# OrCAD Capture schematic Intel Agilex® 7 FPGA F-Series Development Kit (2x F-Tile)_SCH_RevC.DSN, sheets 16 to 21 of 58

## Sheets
16 PG16 AGX BANK 3A - General IOs: size C
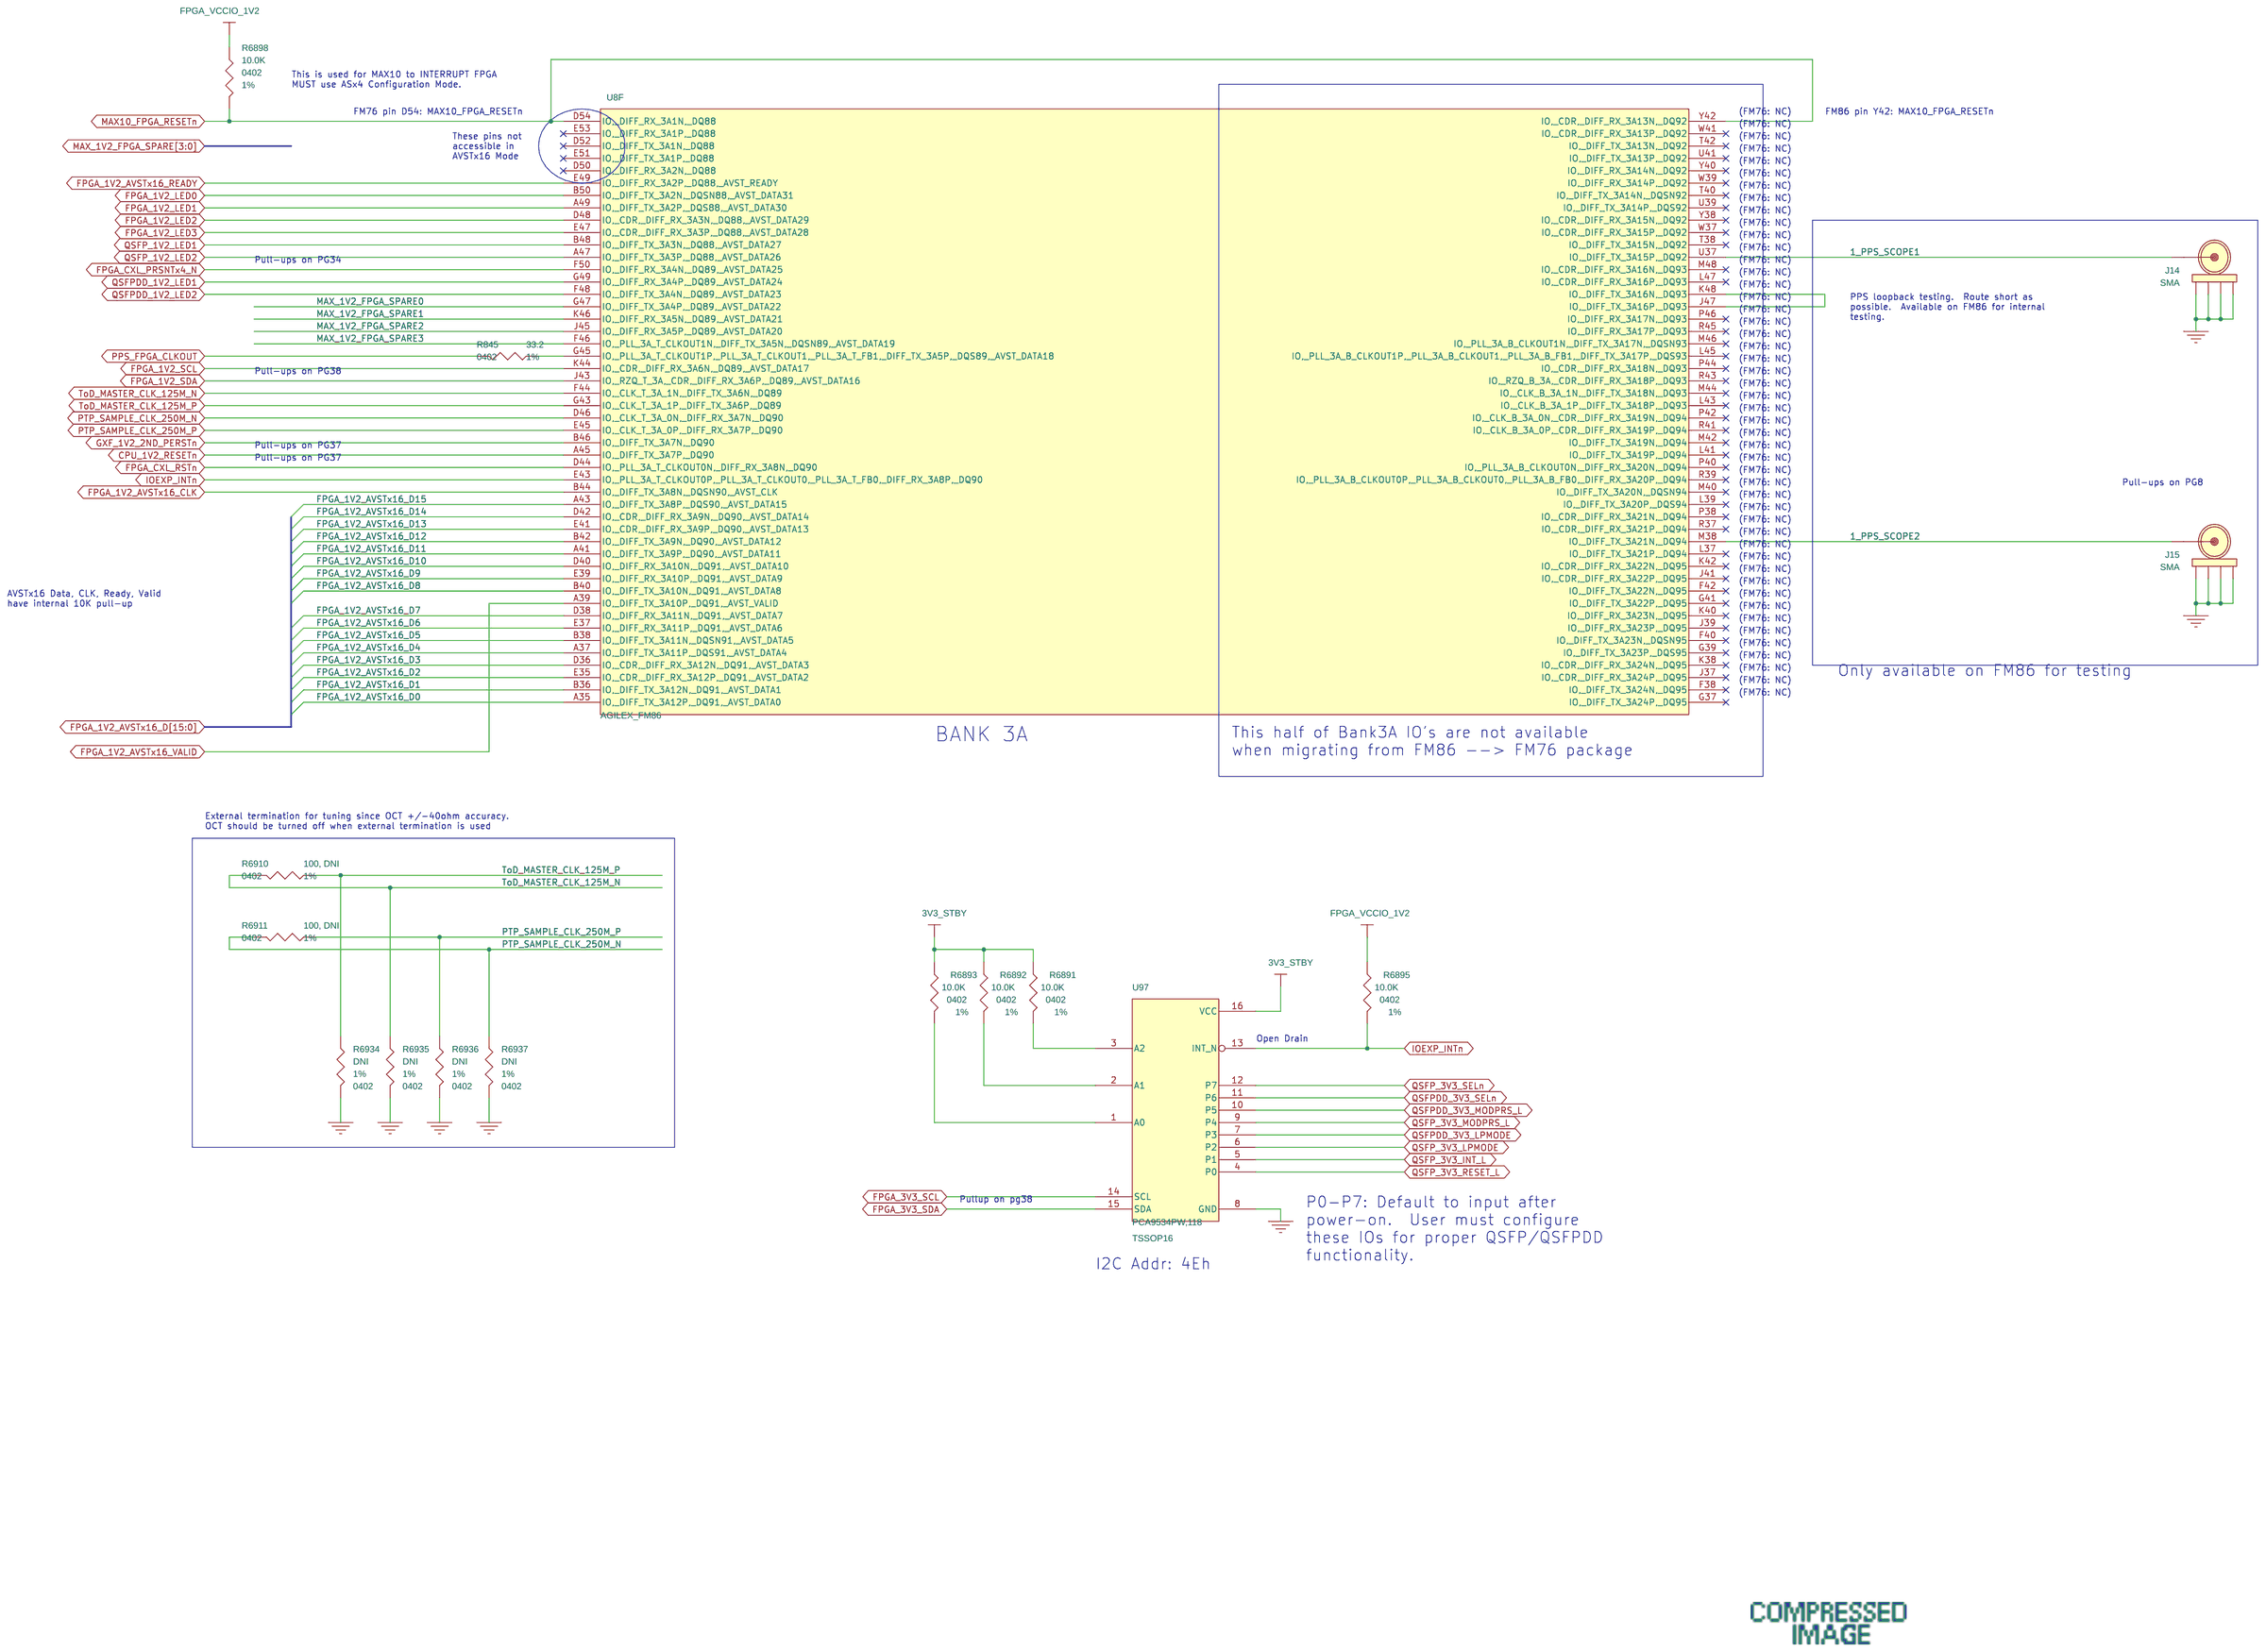
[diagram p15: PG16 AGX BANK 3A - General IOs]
17 PG17 AGX BANK 3B - Unused IOs: size C
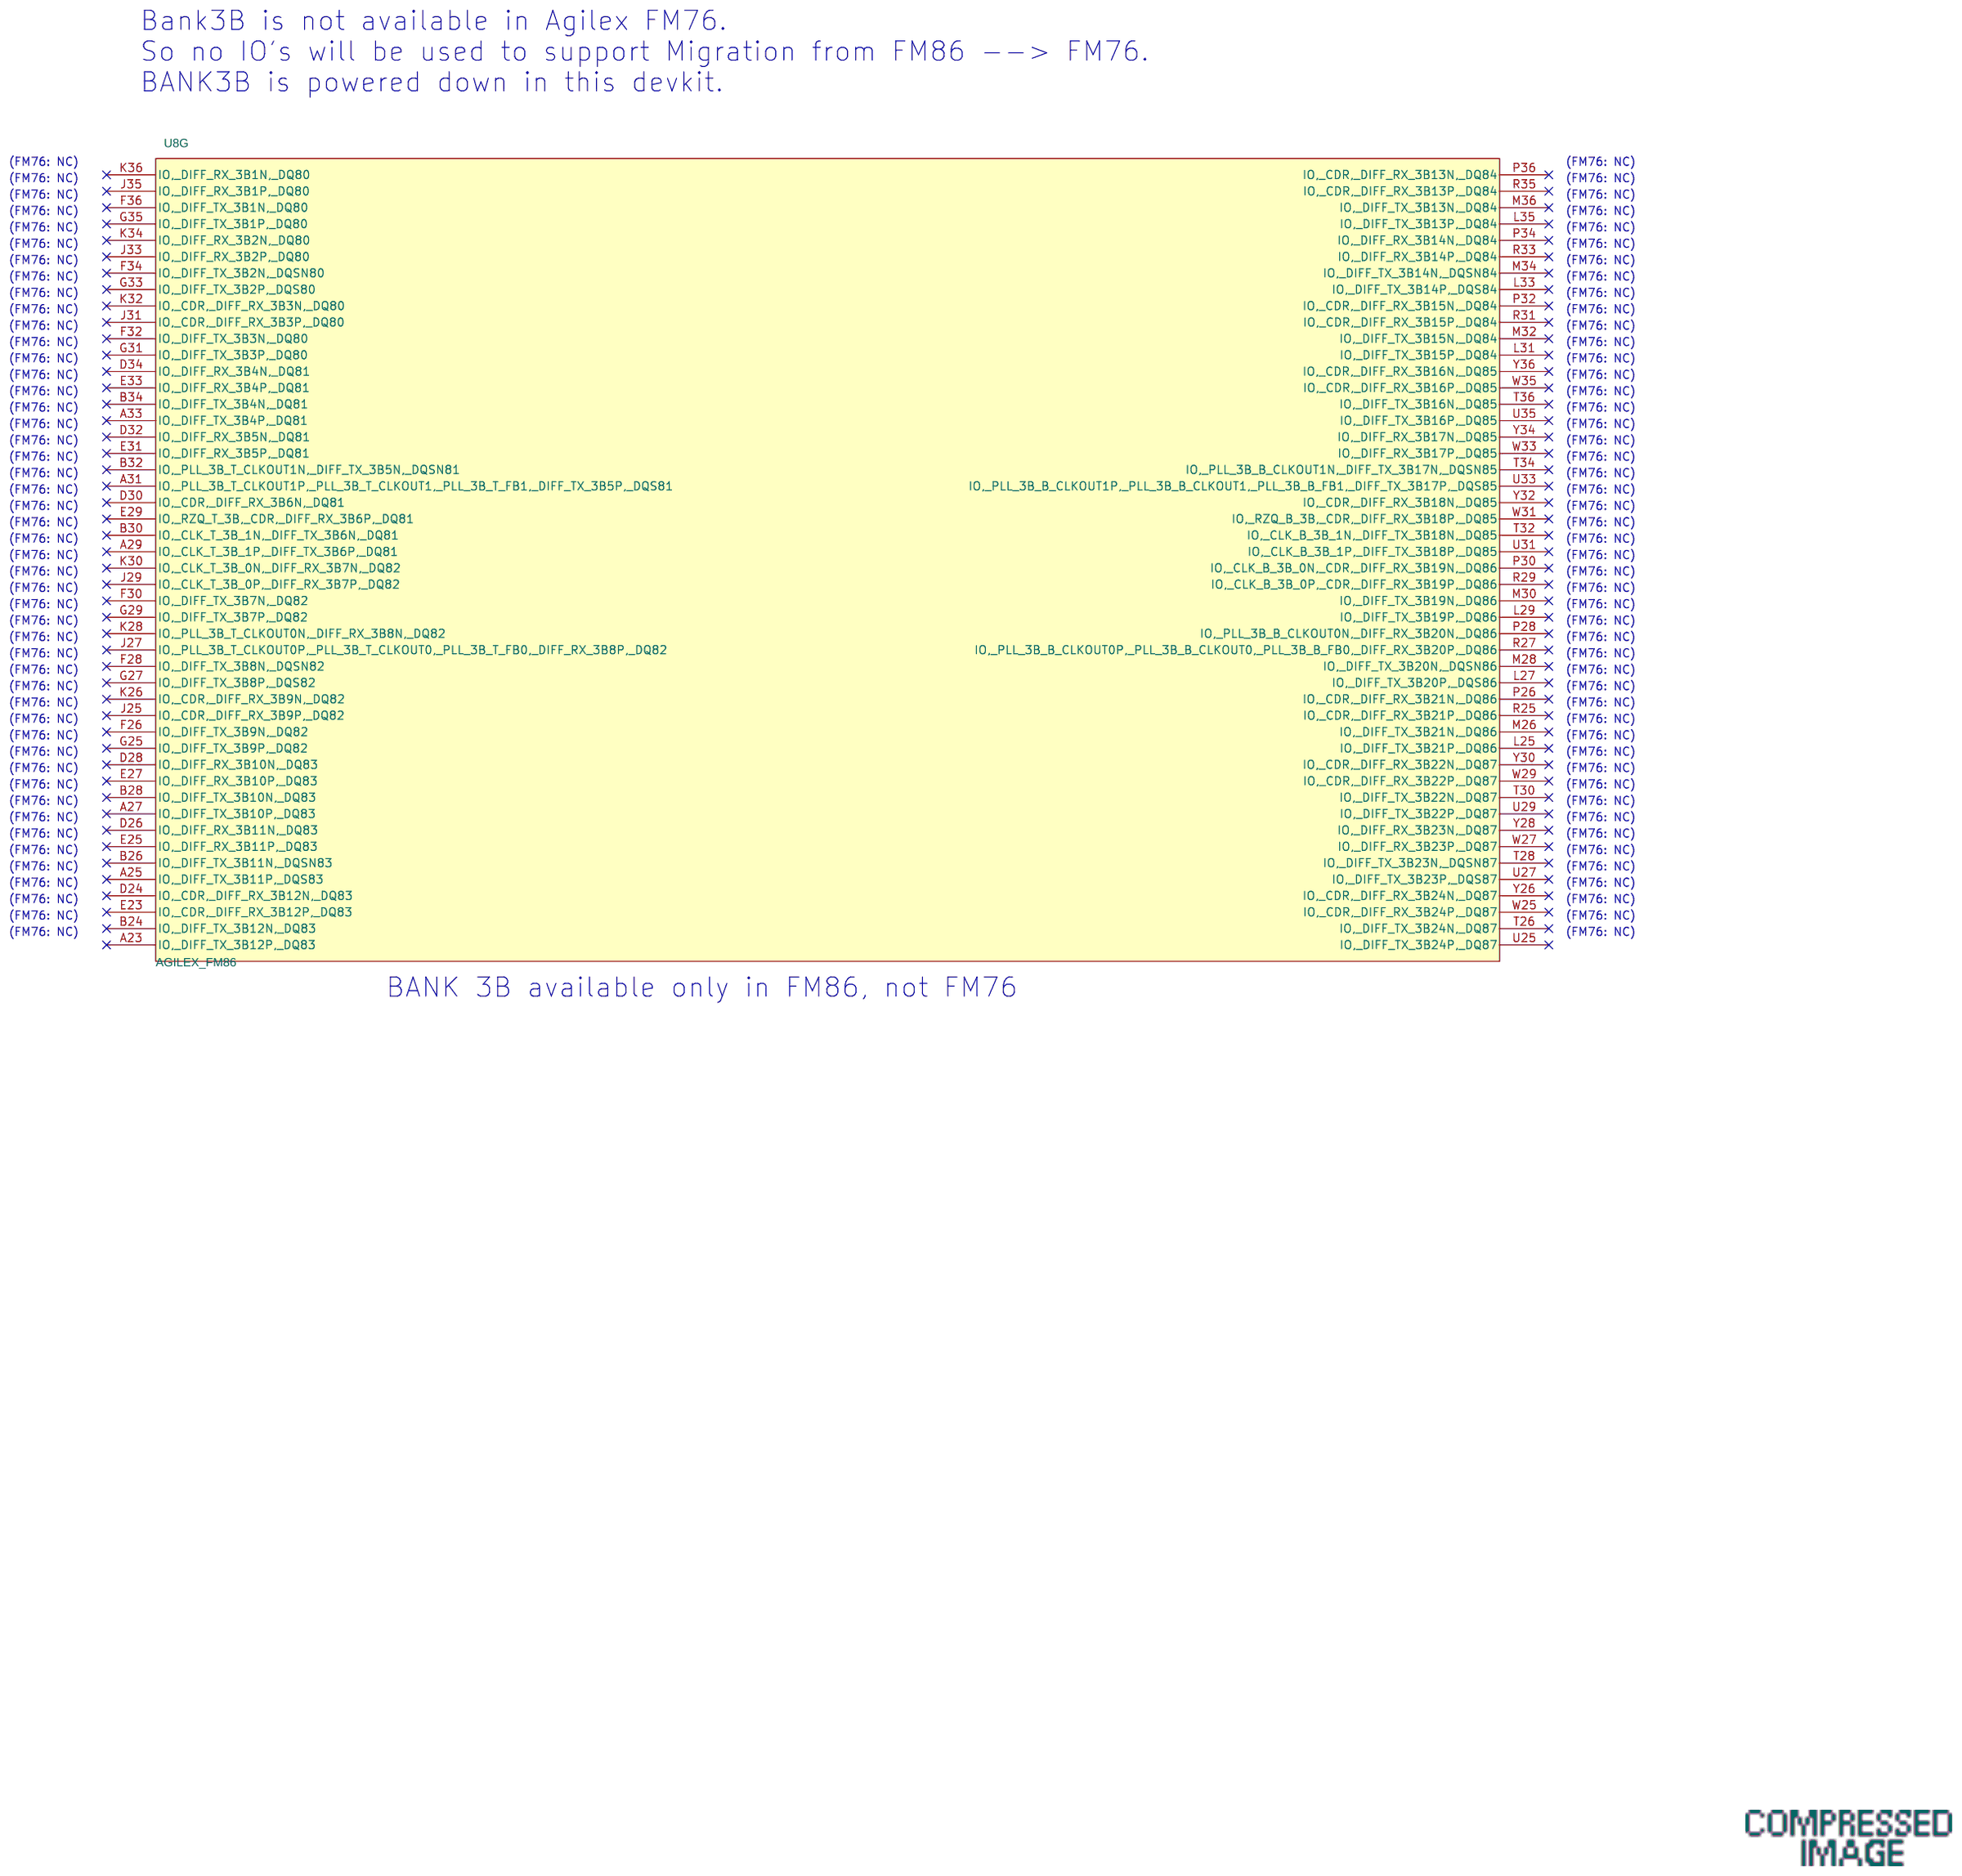
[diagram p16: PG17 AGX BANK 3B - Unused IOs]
18 PG18 AGX BANK 3C - Unused IOs: size C
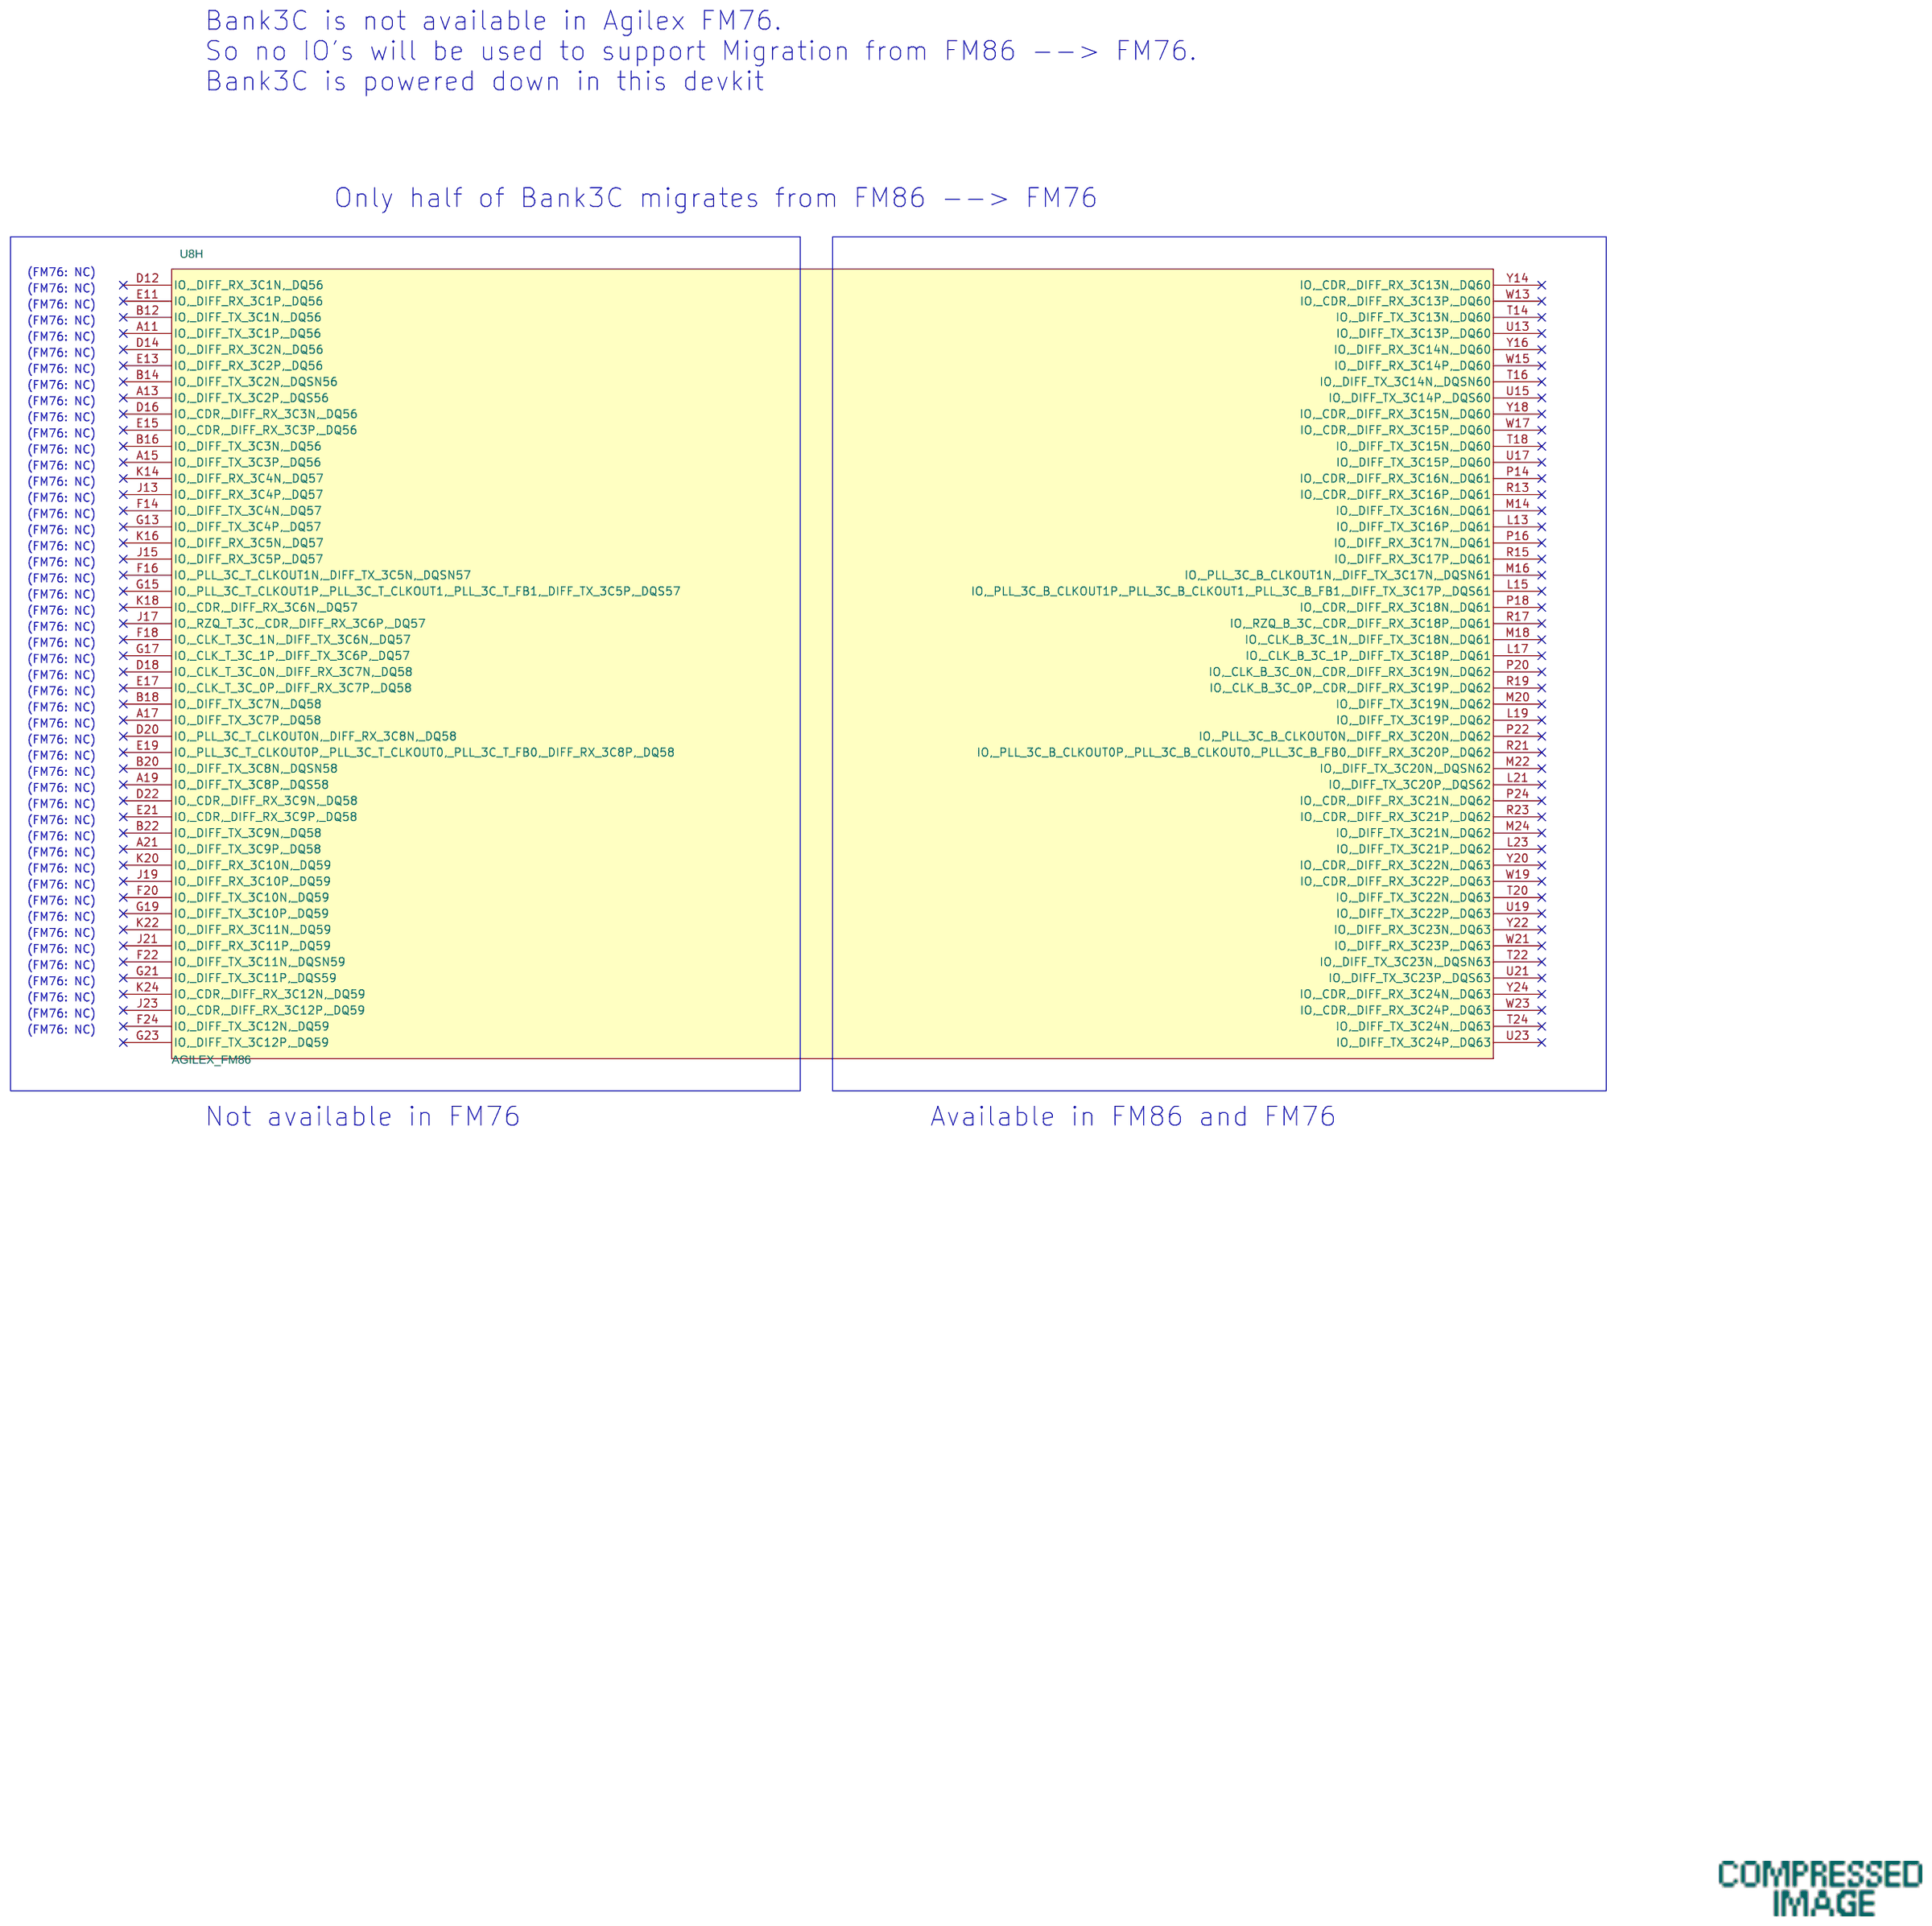
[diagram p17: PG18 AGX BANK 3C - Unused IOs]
19 PG19 AGX BANK 3D - DDR4 COMP: size C
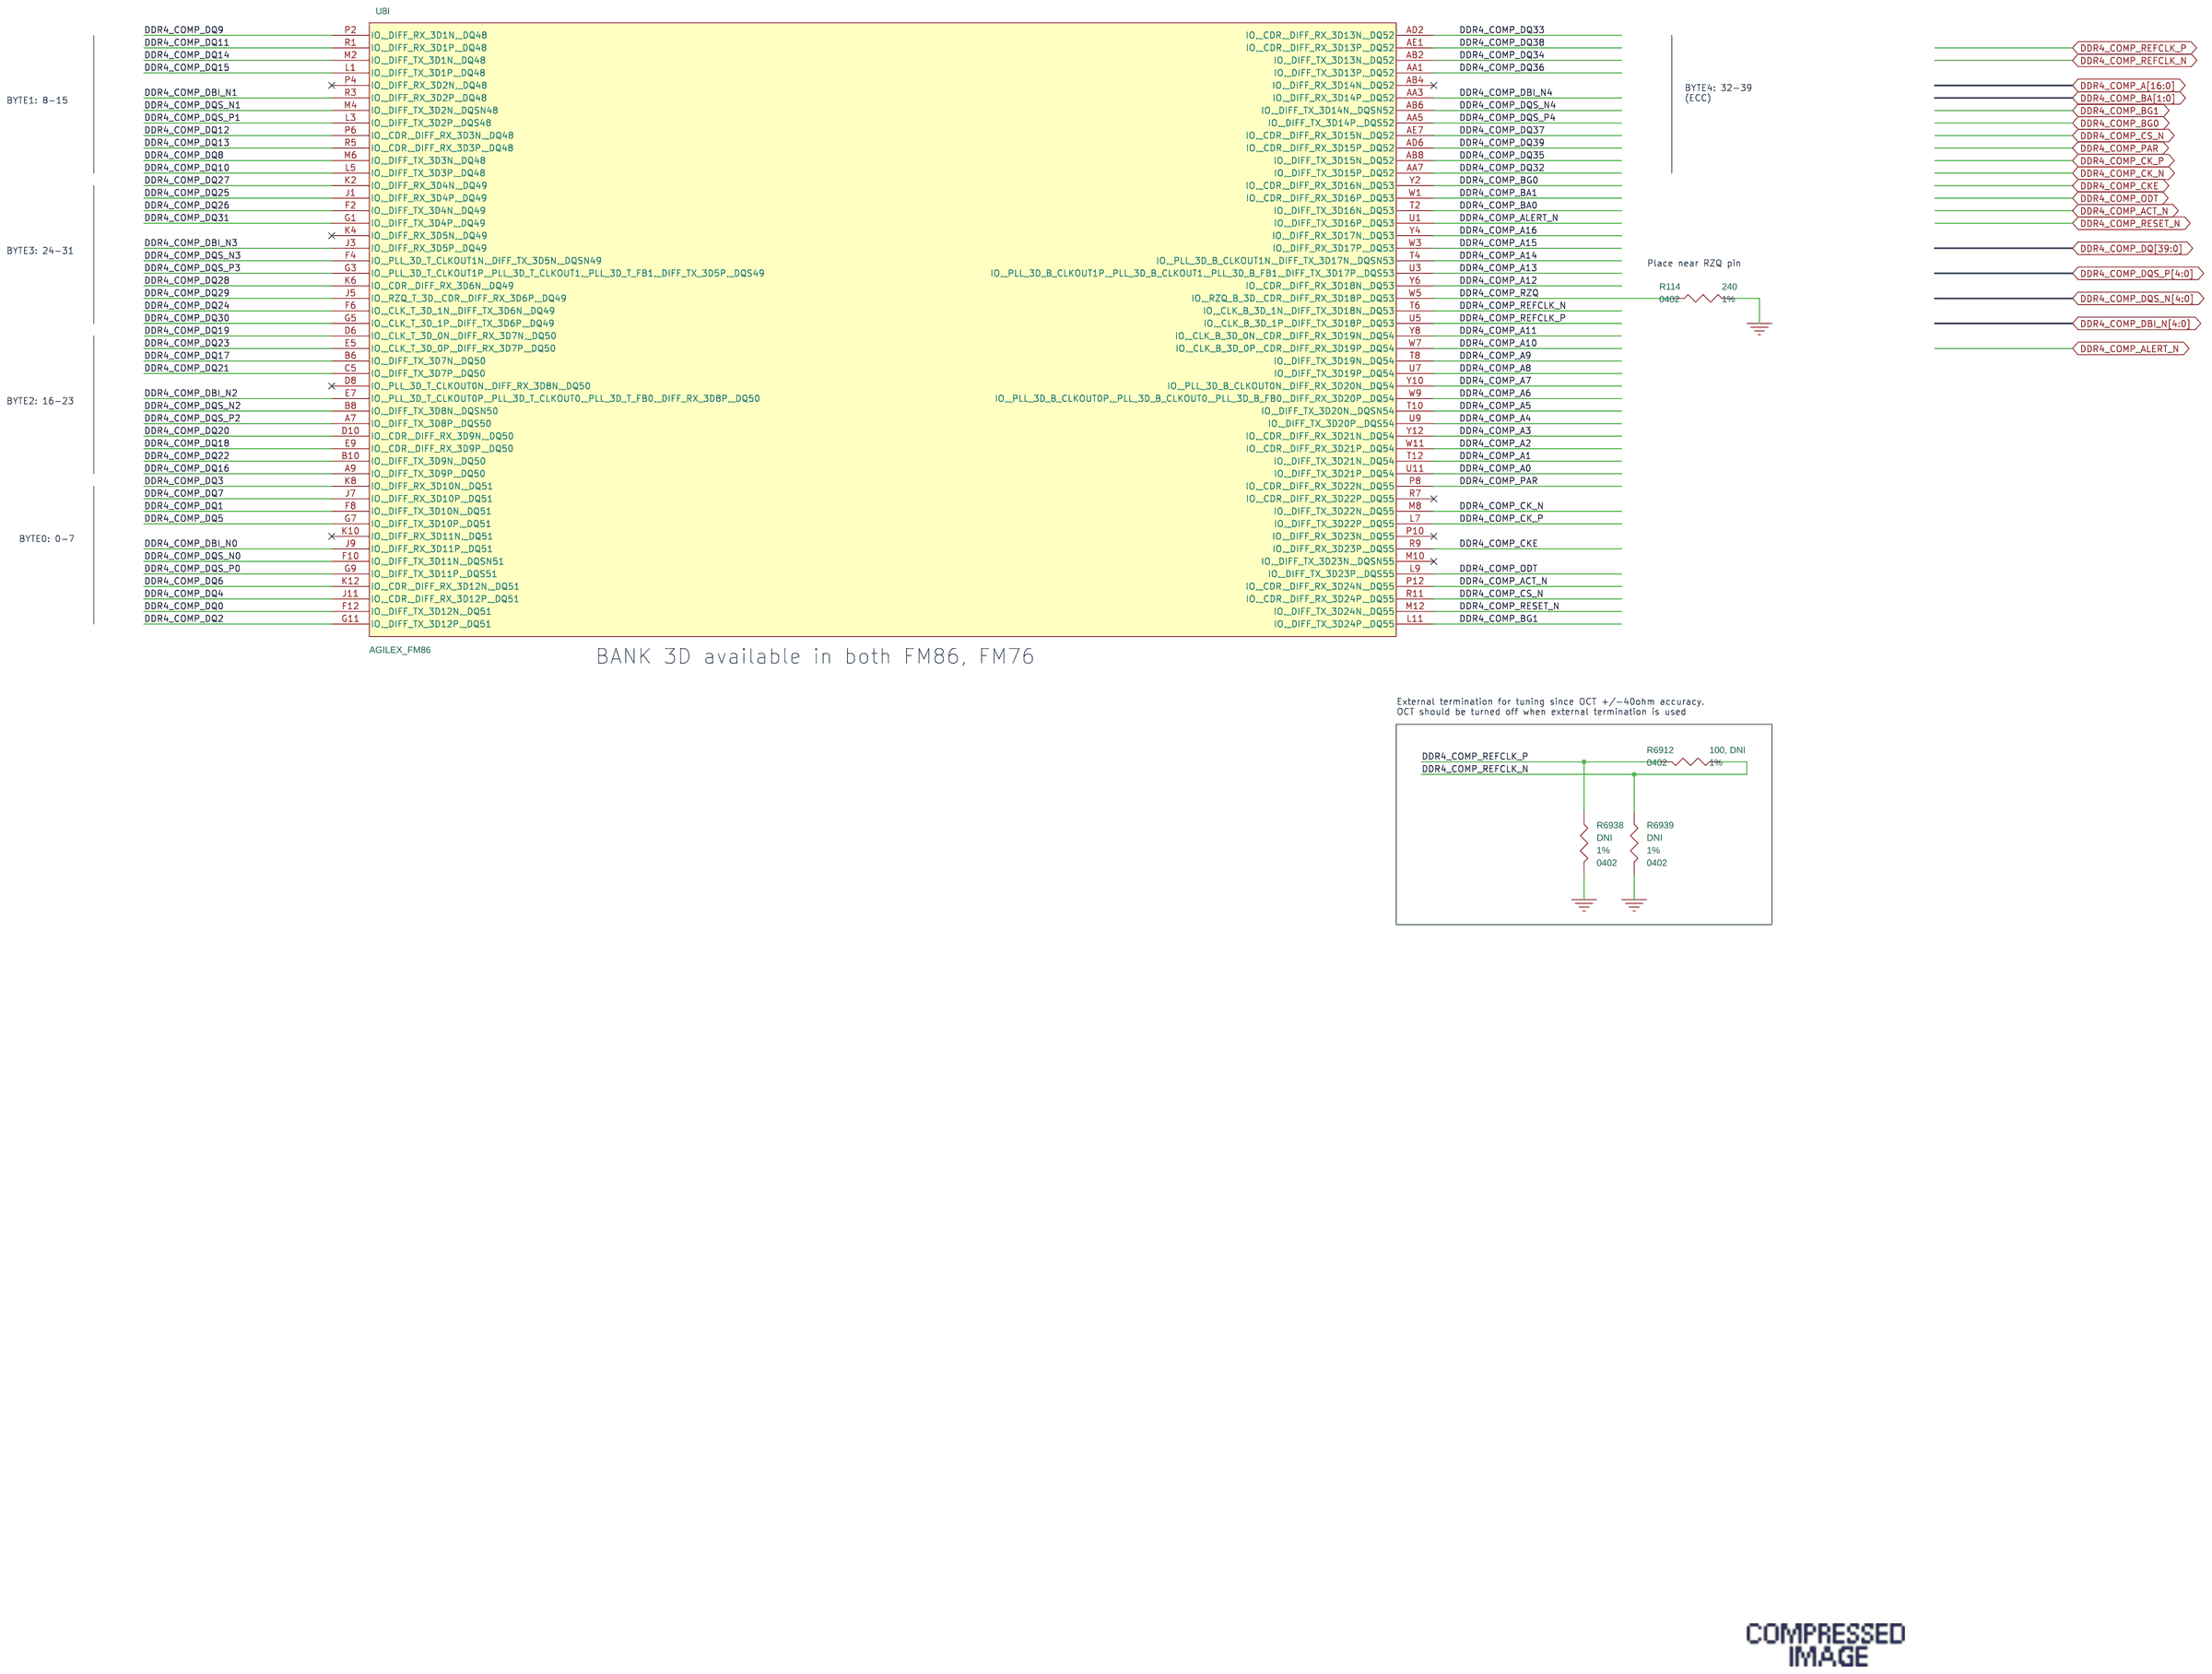
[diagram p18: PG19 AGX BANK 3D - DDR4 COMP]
20 PG20 AGX F-TILE BANK 12C: size C
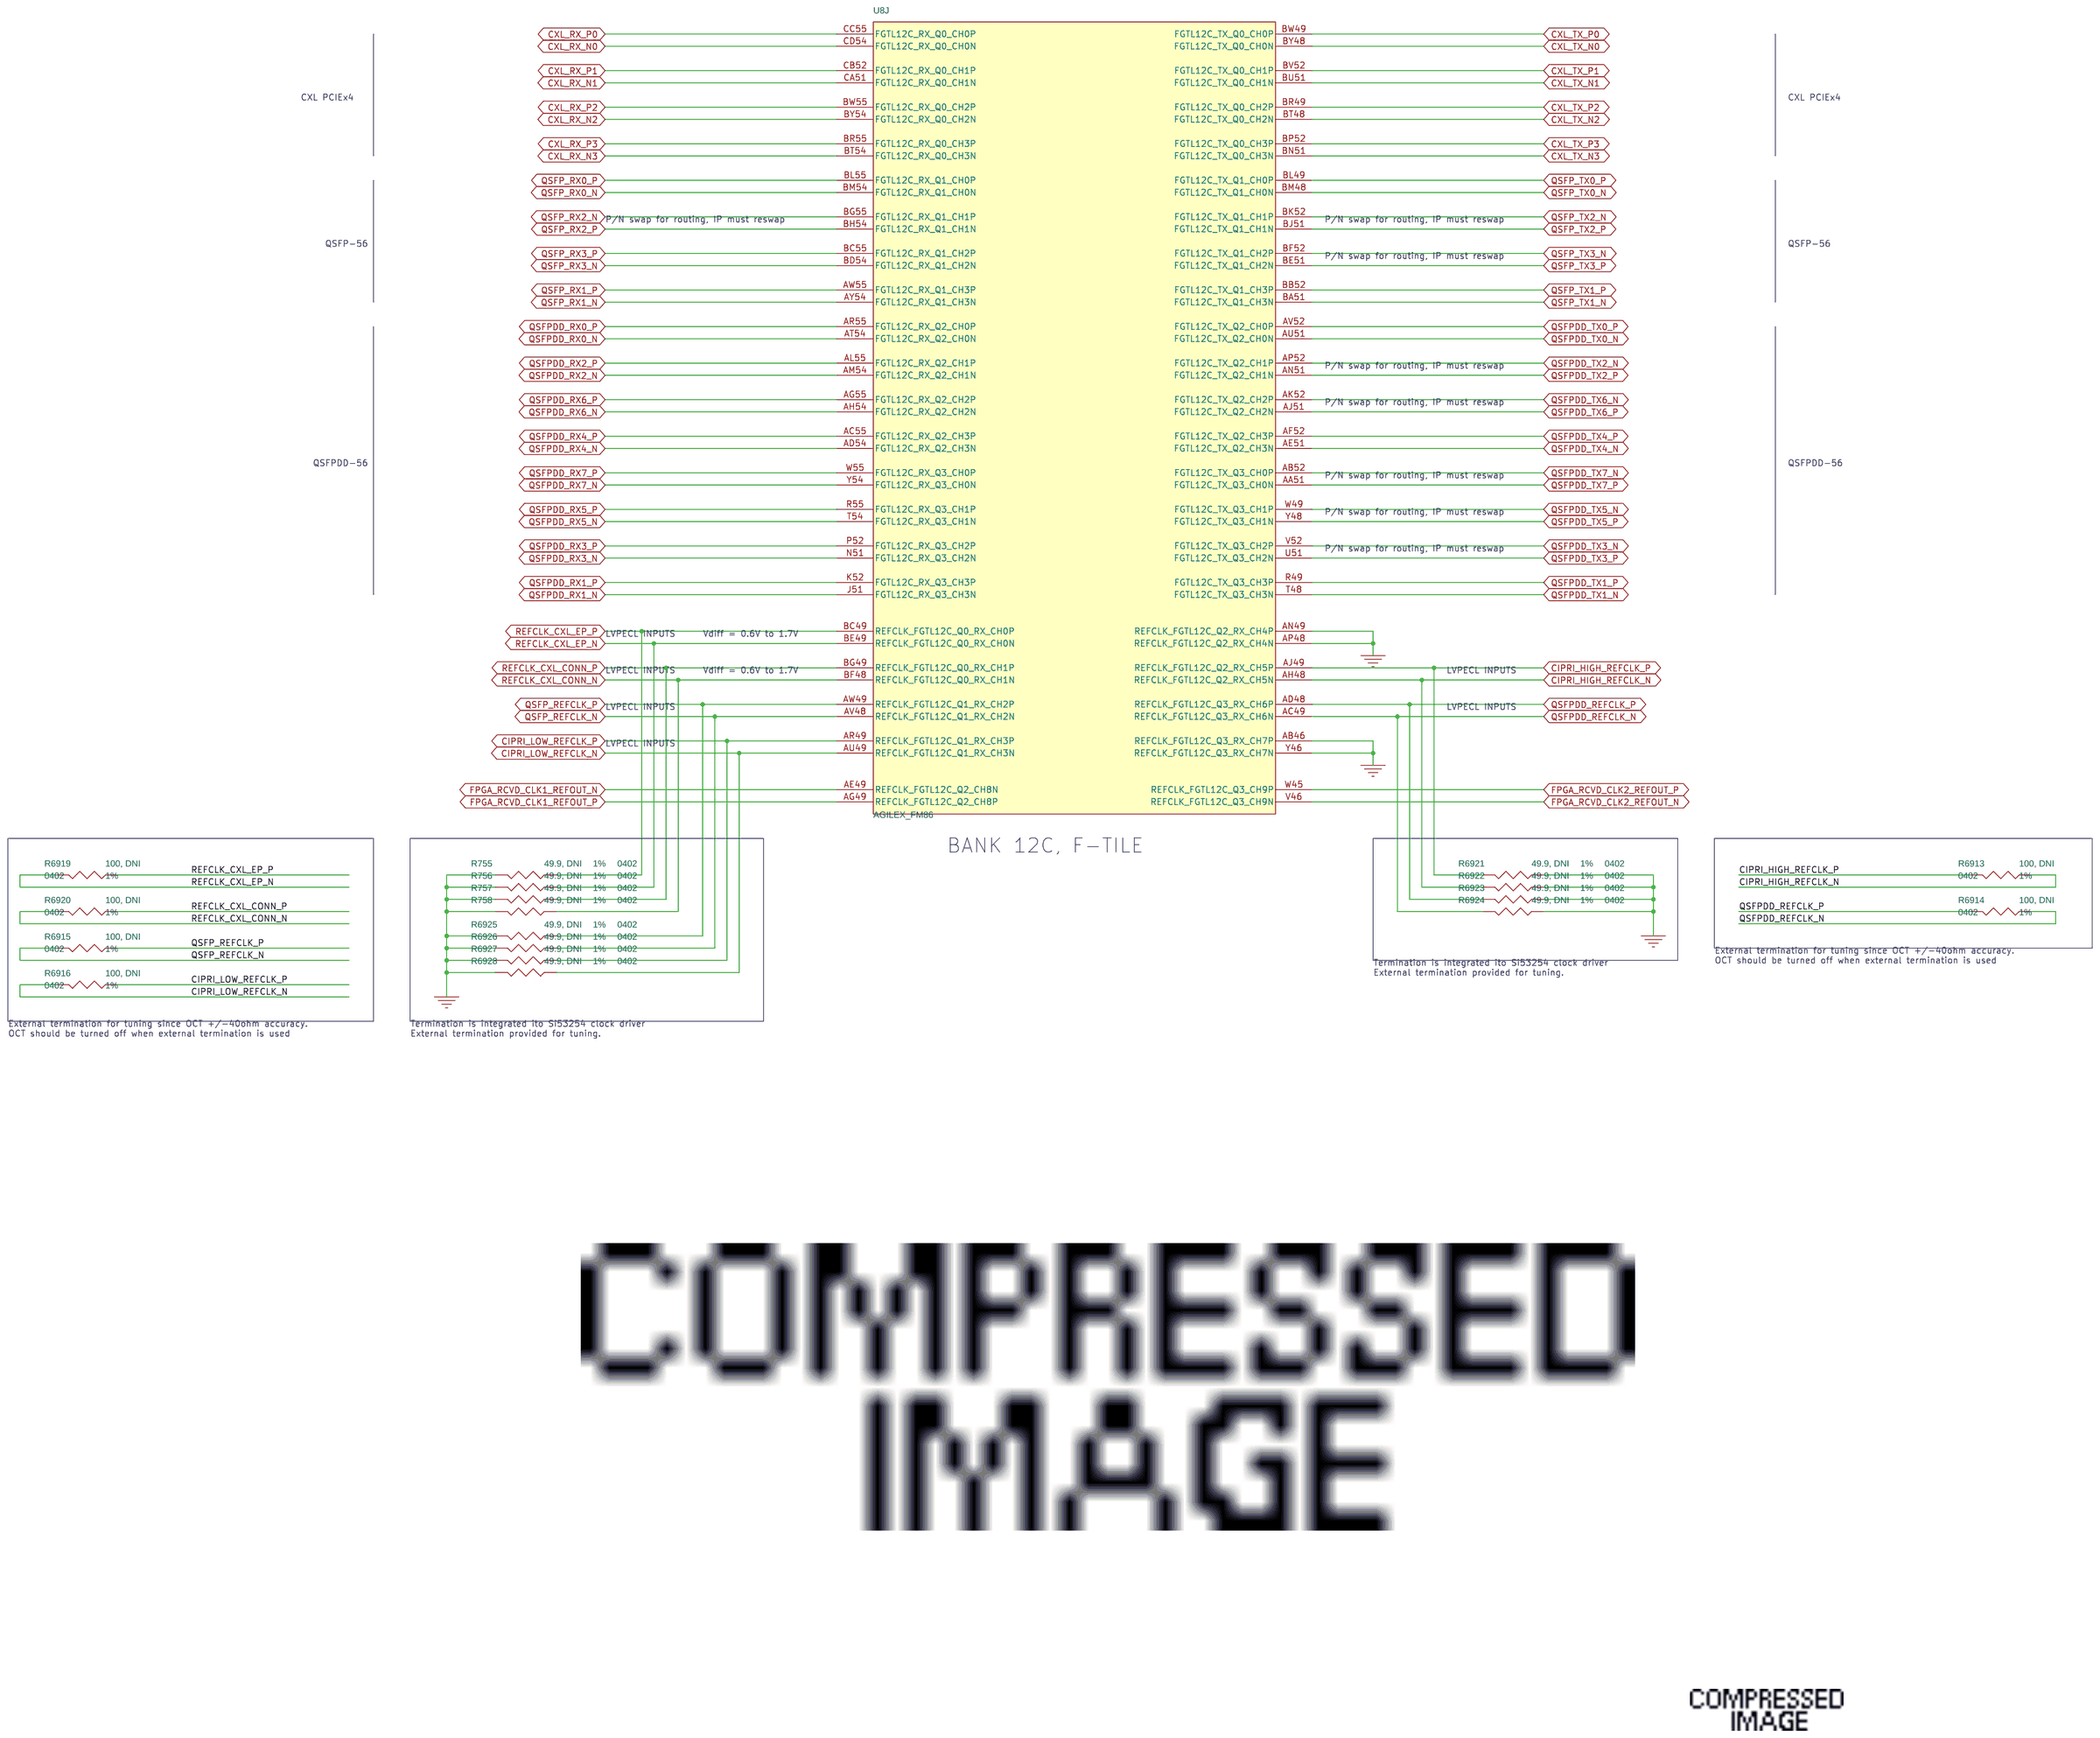
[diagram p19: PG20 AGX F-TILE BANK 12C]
21 PG21 AGX F-TILE BANK 13A: size C
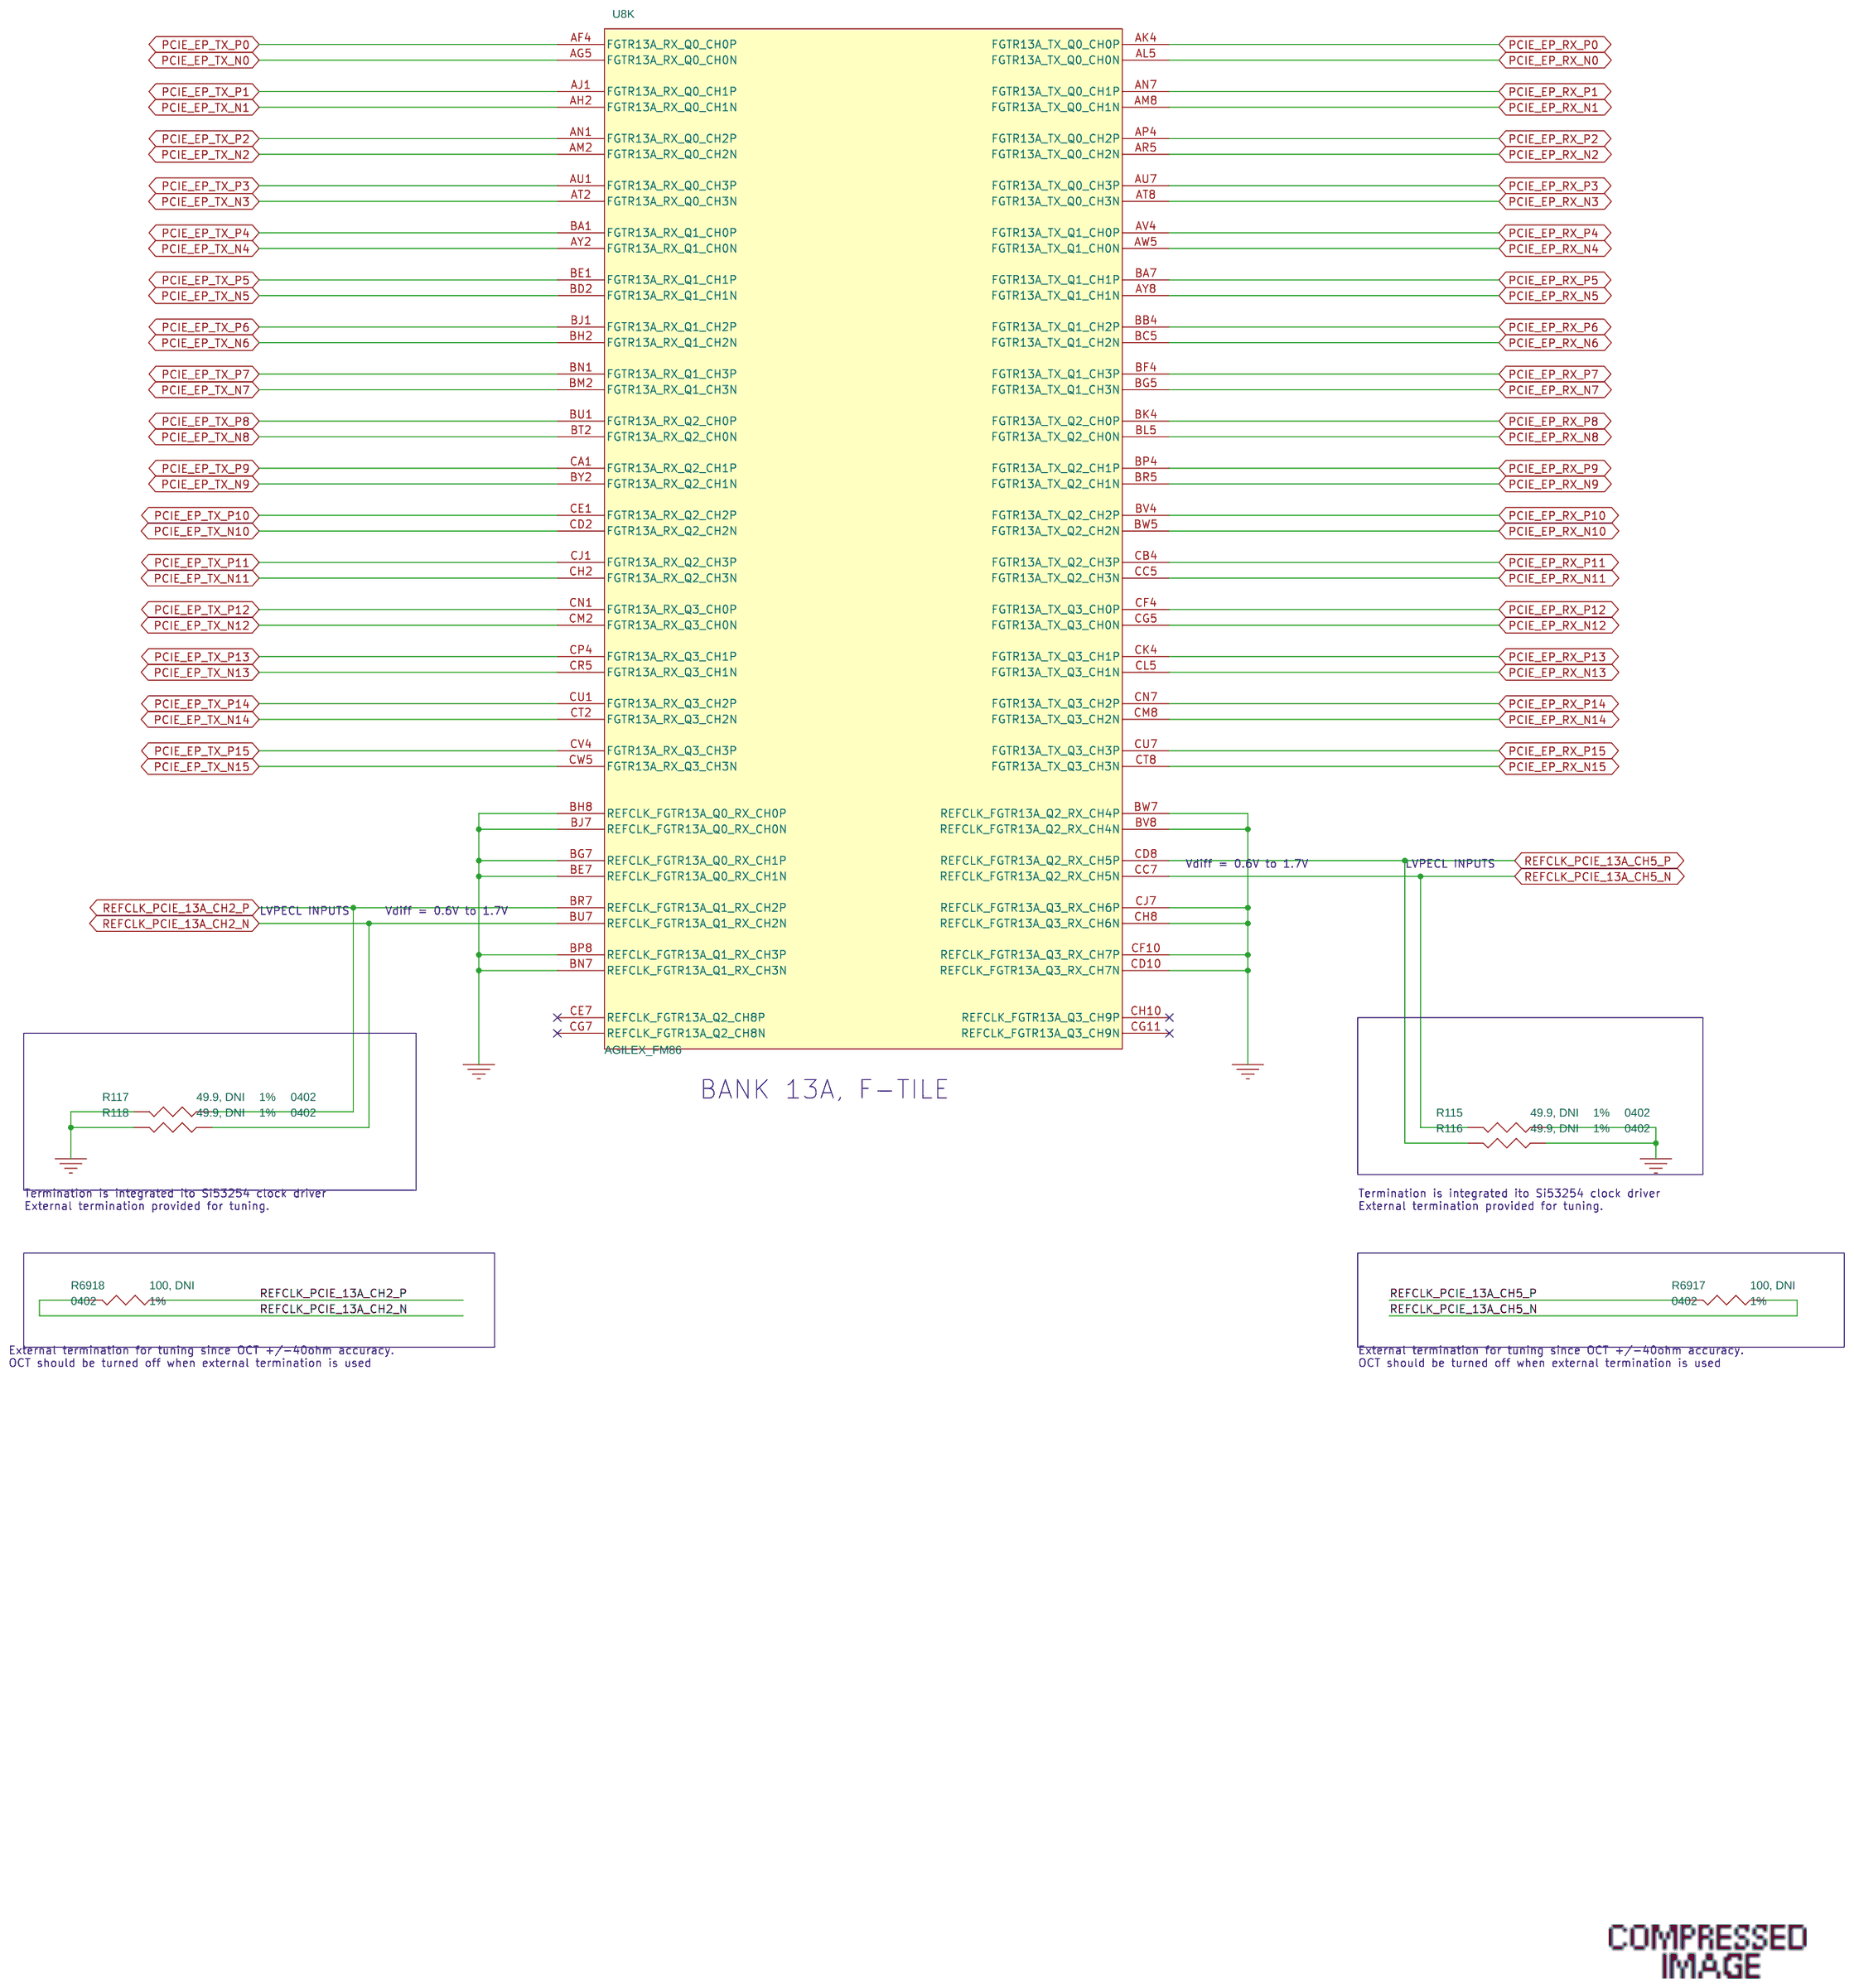
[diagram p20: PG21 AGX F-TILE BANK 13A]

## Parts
sheet PG14 AGX BANK 2E - DDR4 DIMM2
U8  AGILEX_FM86  [FBGA-2340]  (sections A,B,C,D,E,F,G,H,I,J,K,L,M,N,O,P,Q,R,S,T,U,V,W)
sheet PG16 AGX BANK 3A - General IOs
J14  SMA  [SMA_LTI-SASF546-P26-X1]
J15  SMA  [SMA_LTI-SASF546-P26-X1]
R845  33.2  [0402]
R6891  10.0K  [0402]
R6892  10.0K  [0402]
R6893  10.0K  [0402]
R6895  10.0K  [0402]
R6898  10.0K  [0402]
R6910  100, DNI  [0402]
R6911  100, DNI  [0402]
R6934  DNI  [0402]
R6935  DNI  [0402]
R6936  DNI  [0402]
R6937  DNI  [0402]
U97  PCA9534PW,118  [TSSOP16]
sheet PG19 AGX BANK 3D - DDR4 COMP
R114  240  [0402]
R6912  100, DNI  [0402]
R6938  DNI  [0402]
R6939  DNI  [0402]
sheet PG20 AGX F-TILE BANK 12C
R755  49.9, DNI  [0402]
R756  49.9, DNI  [0402]
R757  49.9, DNI  [0402]
R758  49.9, DNI  [0402]
R6913  100, DNI  [0402]
R6914  100, DNI  [0402]
R6915  100, DNI  [0402]
R6916  100, DNI  [0402]
R6919  100, DNI  [0402]
R6920  100, DNI  [0402]
R6921  49.9, DNI  [0402]
R6922  49.9, DNI  [0402]
R6923  49.9, DNI  [0402]
R6924  49.9, DNI  [0402]
R6925  49.9, DNI  [0402]
R6926  49.9, DNI  [0402]
R6927  49.9, DNI  [0402]
R6928  49.9, DNI  [0402]
sheet PG21 AGX F-TILE BANK 13A
R115  49.9, DNI  [0402]
R116  49.9, DNI  [0402]
R117  49.9, DNI  [0402]
R118  49.9, DNI  [0402]
R6917  100, DNI  [0402]
R6918  100, DNI  [0402]

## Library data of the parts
U8 = AGILEX_FM86: IC, FPGA, AGILEX FM86, FBGA2340; Manufacturer: Intel; Manufacturer Part Num: AGFB027R24C2E2VR0
J14 J15 = SMA_CONN: CONN -  SMA VERTICAL GOLD PLATED SMT CENTER CONDUCTOR; Item Num: K10975-001; Manufacturer: Lighthorse Technologies Inc.; Manufacturer Part Num: LTI-SASF546-P26-X1; Speed Part Number: K10975-001
R845 = RESISTOR: RES,33.2 OHMS,1.0%,1/16W,0402; AGILE_LINK: http://sj-agile9app/Agile/PLMServlet?action=OpenEmailObject&classid=10000&objid=146932246; Item Num: J38619-001; LIFECYCLE_PHASE: Active; MFR_LIFECYCLE: Active; Manufacturer: Panasonic; Manufacturer Part Num: ERJ-2RKF33R2X; Num Pins: 2; PART_SUBCLASS: RESISTORS; POWER: 1/16W; RESISTANCE: 10; RoHS Compliant: RoHS Compliant; TOLERANCE: 1%
R6891-R6893 R6895 R6898 = RESISTOR: RES,10.0K OHMS,1.0%,1/16W, 0402; AGILE_LINK: http://sj-agile9app/Agile/PLMServlet?action=OpenEmailObject&classid=10000&objid=146548997; Item Num: K28115-001; LIFECYCLE_PHASE: Active; Lead Free Status: Yes; MFR_LIFECYCLE: Active; Manufacturer: Panasonic; Manufacturer Part Num: ERJ-2RKF1002X; Num Pins: 2; PART_SUBCLASS: RESISTORS; POWER: 1/16W; RoHS Compliant: Yes; TOLERANCE: 1%
R6910-R6920 R6934-R6939 = RESISTOR: RES,100 OHMS,1.0%,1/16W,0402; Item Num: A36092-043; Lead Free Status: Yes; Manufacturer: Yageo; Manufacturer Part Num: RC0402FR-07100RL; Num Pins: 2; Part Class: Resistors; Price: 0; RoHS Compliant: Yes; Tolerance: 1%
U97 = PCA9534RGVR_1: IC, IO EXP, 8bits, TSSOP-16, INT; Item Num: M59810-001; Manufacturer: NXP
R114 = RESISTOR: RES - 240 OHM, 1/16W, 1%, 0402 SMD; Item Num: K15783-001; LIFECYCLE_PHASE: Active; Lead Free Status: Yes; MFR_LIFECYCLE: Active; Manufacturer: Panasonic; Manufacturer Part Num: ERJ-2RKF2400X; Num Pins: 2; PART_SUBCLASS: RESISTORS; RoHS Compliant: Yes; Tolerance: 1%
R115-R118 R755-R758 R6921-R6928 = RESISTOR: RES SMD 49.9 OHM 1% 1/10W 0402; Item Num: K16545-001; LIFECYCLE_PHASE: Active; Lead Free Status: Yes; MFR_LIFECYCLE: Active; Manufacturer: NIC Components Corp.; Manufacturer Part Num: NRC04F49R9TRF; Num Pins: 2; PART_SUBCLASS: RESISTORS; POWER: 1/16W; Part Class: Resistors; RESISTANCE: 49.9; RoHS Compliant: Yes; Tolerance: 1%

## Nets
3V3_STBY: R6891.2 R6892.2 R6893.2 U97.16(VCC) ; also on sheet 8 10 22 28 32 34 36 37 38 40 41 48 49 50 51 52 53 54 58
GND: J14.2 J14.3 J14.4 J14.5 J15.2 J15.3 J15.4 J15.5 R114.1 R115.1 R116.1 R117.2 R118.2 R755.2 R756.2 R757.2 R758.2 R6921.1 R6922.1 R6923.1 R6924.1 R6925.2 R6926.2 R6927.2 R6928.2 R6934.2 R6935.2 R6936.2 R6937.2 R6938.2 R6939.2 U8.AB46(REFCLK_FGTL12C_Q3_RX_CH7P) U8.AN49(REFCLK_FGTL12C_Q2_RX_CH4P) U8.AP48(REFCLK_FGTL12C_Q2_RX_CH4N) U8.BE7(REFCLK_FGTR13A_Q0_RX_CH1N) U8.BG7(REFCLK_FGTR13A_Q0_RX_CH1P) U8.BH8(REFCLK_FGTR13A_Q0_RX_CH0P) U8.BJ7(REFCLK_FGTR13A_Q0_RX_CH0N) U8.BN7(REFCLK_FGTR13A_Q1_RX_CH3N) U8.BP8(REFCLK_FGTR13A_Q1_RX_CH3P) U8.BV8(REFCLK_FGTR13A_Q2_RX_CH4N) U8.BW7(REFCLK_FGTR13A_Q2_RX_CH4P) U8.CD10(REFCLK_FGTR13A_Q3_RX_CH7N) U8.CF10(REFCLK_FGTR13A_Q3_RX_CH7P) U8.CH8(REFCLK_FGTR13A_Q3_RX_CH6N) U8.CJ7(REFCLK_FGTR13A_Q3_RX_CH6P) U8.Y46(REFCLK_FGTL12C_Q3_RX_CH7N) U97.8(GND) ; also on sheet 8 9 10 11 12 13 15 22 23 24 25 26 27 28 29 30 31 32 33 34 35 36 37 38 39 40 41 42 43 44 45 46 47 48 49 50 51 52 53 54 55 56 58
1_PPS_SCOPE1: J14.1 U8.U37(IO,_DIFF_TX_3A15P,_DQ92)
1_PPS_SCOPE2: J15.1 U8.M38(IO,_DIFF_TX_3A21N,_DQ94)
CIPRI_HIGH_REFCLK_N: R6913.1 R6922.2 U8.AH48(REFCLK_FGTL12C_Q2_RX_CH5N) ; also on sheet 32
CIPRI_HIGH_REFCLK_P: R6913.2 R6921.2 U8.AJ49(REFCLK_FGTL12C_Q2_RX_CH5P) ; also on sheet 32
CIPRI_LOW_REFCLK_N: R6916.2 R6928.1 U8.AU49(REFCLK_FGTL12C_Q1_RX_CH3N) ; also on sheet 32
CIPRI_LOW_REFCLK_P: R6916.1 R6927.1 U8.AR49(REFCLK_FGTL12C_Q1_RX_CH3P) ; also on sheet 32
CPU_1V2_RESETn: U8.A45(IO,_DIFF_TX_3A7P,_DQ90) ; also on sheet 34
CXL_RX_N0: U8.CD54(FGTL12C_RX_Q0_CH0N) ; also on sheet 31
CXL_RX_N1: U8.CA51(FGTL12C_RX_Q0_CH1N) ; also on sheet 31
CXL_RX_N2: U8.BY54(FGTL12C_RX_Q0_CH2N) ; also on sheet 31
CXL_RX_N3: U8.BT54(FGTL12C_RX_Q0_CH3N) ; also on sheet 31
CXL_RX_P0: U8.CC55(FGTL12C_RX_Q0_CH0P) ; also on sheet 31
CXL_RX_P1: U8.CB52(FGTL12C_RX_Q0_CH1P) ; also on sheet 31
CXL_RX_P2: U8.BW55(FGTL12C_RX_Q0_CH2P) ; also on sheet 31
CXL_RX_P3: U8.BR55(FGTL12C_RX_Q0_CH3P) ; also on sheet 31
CXL_TX_N0: U8.BY48(FGTL12C_TX_Q0_CH0N) ; also on sheet 31
CXL_TX_N1: U8.BU51(FGTL12C_TX_Q0_CH1N) ; also on sheet 31
CXL_TX_N2: U8.BT48(FGTL12C_TX_Q0_CH2N) ; also on sheet 31
CXL_TX_N3: U8.BN51(FGTL12C_TX_Q0_CH3N) ; also on sheet 31
CXL_TX_P0: U8.BW49(FGTL12C_TX_Q0_CH0P) ; also on sheet 31
CXL_TX_P1: U8.BV52(FGTL12C_TX_Q0_CH1P) ; also on sheet 31
CXL_TX_P2: U8.BR49(FGTL12C_TX_Q0_CH2P) ; also on sheet 31
CXL_TX_P3: U8.BP52(FGTL12C_TX_Q0_CH3P) ; also on sheet 31
DDR4_COMP_A0: U8.U11(IO,_DIFF_TX_3D21P,_DQ54) ; also on sheet 25 26 27
DDR4_COMP_A1: U8.T12(IO,_DIFF_TX_3D21N,_DQ54) ; also on sheet 25 26 27
DDR4_COMP_A2: U8.W11(IO,_CDR,_DIFF_RX_3D21P,_DQ54) ; also on sheet 25 26 27
DDR4_COMP_A3: U8.Y12(IO,_CDR,_DIFF_RX_3D21N,_DQ54) ; also on sheet 25 26 27
DDR4_COMP_A4: U8.U9(IO,_DIFF_TX_3D20P,_DQS54) ; also on sheet 25 26 27
DDR4_COMP_A5: U8.T10(IO,_DIFF_TX_3D20N,_DQSN54) ; also on sheet 25 26 27
DDR4_COMP_A6: U8.W9(IO,_PLL_3D_B_CLKOUT0P,_PLL_3D_B_CLKOUT0,_PLL_3D_B_FB0,_DIFF_RX_3D20P,_DQ54) ; also on sheet 25 26 27
DDR4_COMP_A7: U8.Y10(IO,_PLL_3D_B_CLKOUT0N,_DIFF_RX_3D20N,_DQ54) ; also on sheet 25 26 27
DDR4_COMP_A8: U8.U7(IO,_DIFF_TX_3D19P,_DQ54) ; also on sheet 25 26 27
DDR4_COMP_A9: U8.T8(IO,_DIFF_TX_3D19N,_DQ54) ; also on sheet 25 26 27
DDR4_COMP_A10: U8.W7(IO,_CLK_B_3D_0P,_CDR,_DIFF_RX_3D19P,_DQ54) ; also on sheet 25 26 27
DDR4_COMP_A11: U8.Y8(IO,_CLK_B_3D_0N,_CDR,_DIFF_RX_3D19N,_DQ54) ; also on sheet 25 26 27
DDR4_COMP_A12: U8.Y6(IO,_CDR,_DIFF_RX_3D18N,_DQ53) ; also on sheet 25 26 27
DDR4_COMP_A13: U8.U3(IO,_PLL_3D_B_CLKOUT1P,_PLL_3D_B_CLKOUT1,_PLL_3D_B_FB1,_DIFF_TX_3D17P,_DQS53) ; also on sheet 25 26 27
DDR4_COMP_A14: U8.T4(IO,_PLL_3D_B_CLKOUT1N,_DIFF_TX_3D17N,_DQSN53) ; also on sheet 25 26 27
DDR4_COMP_A15: U8.W3(IO,_DIFF_RX_3D17P,_DQ53) ; also on sheet 25 26 27
DDR4_COMP_A16: U8.Y4(IO,_DIFF_RX_3D17N,_DQ53) ; also on sheet 25 26 27
DDR4_COMP_ACT_N: U8.P12(IO,_CDR,_DIFF_RX_3D24N,_DQ55) ; also on sheet 25 26 27
DDR4_COMP_ALERT_N: U8.U1(IO,_DIFF_TX_3D16P,_DQ53) ; also on sheet 25 26 27
DDR4_COMP_BA0: U8.T2(IO,_DIFF_TX_3D16N,_DQ53) ; also on sheet 25 26 27
DDR4_COMP_BA1: U8.W1(IO,_CDR,_DIFF_RX_3D16P,_DQ53) ; also on sheet 25 26 27
DDR4_COMP_BG0: U8.Y2(IO,_CDR,_DIFF_RX_3D16N,_DQ53) ; also on sheet 25 26 27
DDR4_COMP_BG1: U8.L11(IO,_DIFF_TX_3D24P,_DQ55) ; also on sheet 25 26 27
DDR4_COMP_CK_N: U8.M8(IO,_DIFF_TX_3D22N,_DQ55) ; also on sheet 25 26 27
DDR4_COMP_CK_P: U8.L7(IO,_DIFF_TX_3D22P,_DQ55) ; also on sheet 25 26 27
DDR4_COMP_CKE: U8.R9(IO,_DIFF_RX_3D23P,_DQ55) ; also on sheet 25 26 27
DDR4_COMP_CS_N: U8.R11(IO,_CDR,_DIFF_RX_3D24P,_DQ55) ; also on sheet 25 26 27
DDR4_COMP_DBI_N0: U8.J9(IO,_DIFF_RX_3D11P,_DQ51) ; also on sheet 27
DDR4_COMP_DBI_N1: U8.R3(IO,_DIFF_RX_3D2P,_DQ48) ; also on sheet 25
DDR4_COMP_DBI_N2: U8.E7(IO,_PLL_3D_T_CLKOUT0P,_PLL_3D_T_CLKOUT0,_PLL_3D_T_FB0,_DIFF_RX_3D8P,_DQ50) ; also on sheet 26
DDR4_COMP_DBI_N3: U8.J3(IO,_DIFF_RX_3D5P,_DQ49) ; also on sheet 26
DDR4_COMP_DBI_N4: U8.AA3(IO,_DIFF_RX_3D14P,_DQ52) ; also on sheet 25
DDR4_COMP_DQ0: U8.F12(IO,_DIFF_TX_3D12N,_DQ51) ; also on sheet 27
DDR4_COMP_DQ1: U8.F8(IO,_DIFF_TX_3D10N,_DQ51) ; also on sheet 27
DDR4_COMP_DQ2: U8.G11(IO,_DIFF_TX_3D12P,_DQ51) ; also on sheet 27
DDR4_COMP_DQ3: U8.K8(IO,_DIFF_RX_3D10N,_DQ51) ; also on sheet 27
DDR4_COMP_DQ4: U8.J11(IO,_CDR,_DIFF_RX_3D12P,_DQ51) ; also on sheet 27
DDR4_COMP_DQ5: U8.G7(IO,_DIFF_TX_3D10P,_DQ51) ; also on sheet 27
DDR4_COMP_DQ6: U8.K12(IO,_CDR,_DIFF_RX_3D12N,_DQ51) ; also on sheet 27
DDR4_COMP_DQ7: U8.J7(IO,_DIFF_RX_3D10P,_DQ51) ; also on sheet 27
DDR4_COMP_DQ8: U8.M6(IO,_DIFF_TX_3D3N,_DQ48) ; also on sheet 25
DDR4_COMP_DQ9: U8.P2(IO,_DIFF_RX_3D1N,_DQ48) ; also on sheet 25
DDR4_COMP_DQ10: U8.L5(IO,_DIFF_TX_3D3P,_DQ48) ; also on sheet 25
DDR4_COMP_DQ11: U8.R1(IO,_DIFF_RX_3D1P,_DQ48) ; also on sheet 25
DDR4_COMP_DQ12: U8.P6(IO,_CDR,_DIFF_RX_3D3N,_DQ48) ; also on sheet 25
DDR4_COMP_DQ13: U8.R5(IO,_CDR,_DIFF_RX_3D3P,_DQ48) ; also on sheet 25
DDR4_COMP_DQ14: U8.M2(IO,_DIFF_TX_3D1N,_DQ48) ; also on sheet 25
DDR4_COMP_DQ15: U8.L1(IO,_DIFF_TX_3D1P,_DQ48) ; also on sheet 25
DDR4_COMP_DQ16: U8.A9(IO,_DIFF_TX_3D9P,_DQ50) ; also on sheet 26
DDR4_COMP_DQ17: U8.B6(IO,_DIFF_TX_3D7N,_DQ50) ; also on sheet 26
DDR4_COMP_DQ18: U8.E9(IO,_CDR,_DIFF_RX_3D9P,_DQ50) ; also on sheet 26
DDR4_COMP_DQ19: U8.D6(IO,_CLK_T_3D_0N,_DIFF_RX_3D7N,_DQ50) ; also on sheet 26
DDR4_COMP_DQ20: U8.D10(IO,_CDR,_DIFF_RX_3D9N,_DQ50) ; also on sheet 26
DDR4_COMP_DQ21: U8.C5(IO,_DIFF_TX_3D7P,_DQ50) ; also on sheet 26
DDR4_COMP_DQ22: U8.B10(IO,_DIFF_TX_3D9N,_DQ50) ; also on sheet 26
DDR4_COMP_DQ23: U8.E5(IO,_CLK_T_3D_0P,_DIFF_RX_3D7P,_DQ50) ; also on sheet 26
DDR4_COMP_DQ24: U8.F6(IO,_CLK_T_3D_1N,_DIFF_TX_3D6N,_DQ49) ; also on sheet 26
DDR4_COMP_DQ25: U8.J1(IO,_DIFF_RX_3D4P,_DQ49) ; also on sheet 26
DDR4_COMP_DQ26: U8.F2(IO,_DIFF_TX_3D4N,_DQ49) ; also on sheet 26
DDR4_COMP_DQ27: U8.K2(IO,_DIFF_RX_3D4N,_DQ49) ; also on sheet 26
DDR4_COMP_DQ28: U8.K6(IO,_CDR,_DIFF_RX_3D6N,_DQ49) ; also on sheet 26
DDR4_COMP_DQ29: U8.J5(IO,_RZQ_T_3D,_CDR,_DIFF_RX_3D6P,_DQ49) ; also on sheet 26
DDR4_COMP_DQ30: U8.G5(IO,_CLK_T_3D_1P,_DIFF_TX_3D6P,_DQ49) ; also on sheet 26
DDR4_COMP_DQ31: U8.G1(IO,_DIFF_TX_3D4P,_DQ49) ; also on sheet 26
DDR4_COMP_DQ32: U8.AA7(IO,_DIFF_TX_3D15P,_DQ52) ; also on sheet 25
DDR4_COMP_DQ33: U8.AD2(IO,_CDR,_DIFF_RX_3D13N,_DQ52) ; also on sheet 25
DDR4_COMP_DQ34: U8.AB2(IO,_DIFF_TX_3D13N,_DQ52) ; also on sheet 25
DDR4_COMP_DQ35: U8.AB8(IO,_DIFF_TX_3D15N,_DQ52) ; also on sheet 25
DDR4_COMP_DQ36: U8.AA1(IO,_DIFF_TX_3D13P,_DQ52) ; also on sheet 25
DDR4_COMP_DQ37: U8.AE7(IO,_CDR,_DIFF_RX_3D15N,_DQ52) ; also on sheet 25
DDR4_COMP_DQ38: U8.AE1(IO,_CDR,_DIFF_RX_3D13P,_DQ52) ; also on sheet 25
DDR4_COMP_DQ39: U8.AD6(IO,_CDR,_DIFF_RX_3D15P,_DQ52) ; also on sheet 25
DDR4_COMP_DQS_N0: U8.F10(IO,_DIFF_TX_3D11N,_DQSN51) ; also on sheet 27
DDR4_COMP_DQS_N1: U8.M4(IO,_DIFF_TX_3D2N,_DQSN48) ; also on sheet 25
DDR4_COMP_DQS_N2: U8.B8(IO,_DIFF_TX_3D8N,_DQSN50) ; also on sheet 26
DDR4_COMP_DQS_N3: U8.F4(IO,_PLL_3D_T_CLKOUT1N,_DIFF_TX_3D5N,_DQSN49) ; also on sheet 26
DDR4_COMP_DQS_N4: U8.AB6(IO,_DIFF_TX_3D14N,_DQSN52) ; also on sheet 25
DDR4_COMP_DQS_P0: U8.G9(IO,_DIFF_TX_3D11P,_DQS51) ; also on sheet 27
DDR4_COMP_DQS_P1: U8.L3(IO,_DIFF_TX_3D2P,_DQS48) ; also on sheet 25
DDR4_COMP_DQS_P2: U8.A7(IO,_DIFF_TX_3D8P,_DQS50) ; also on sheet 26
DDR4_COMP_DQS_P3: U8.G3(IO,_PLL_3D_T_CLKOUT1P,_PLL_3D_T_CLKOUT1,_PLL_3D_T_FB1,_DIFF_TX_3D5P,_DQS49) ; also on sheet 26
DDR4_COMP_DQS_P4: U8.AA5(IO,_DIFF_TX_3D14P,_DQS52) ; also on sheet 25
DDR4_COMP_ODT: U8.L9(IO,_DIFF_TX_3D23P,_DQS55) ; also on sheet 25 26 27
DDR4_COMP_PAR: U8.P8(IO,_CDR,_DIFF_RX_3D22N,_DQ55) ; also on sheet 25 26 27
DDR4_COMP_REFCLK_N: R6912.1 R6939.1 U8.T6(IO,_CLK_B_3D_1N,_DIFF_TX_3D18N,_DQ53) ; also on sheet 32
DDR4_COMP_REFCLK_P: R6912.2 R6938.1 U8.U5(IO,_CLK_B_3D_1P,_DIFF_TX_3D18P,_DQ53) ; also on sheet 32
DDR4_COMP_RESET_N: U8.M12(IO,_DIFF_TX_3D24N,_DQ55) ; also on sheet 25 26 27
DDR4_COMP_RZQ: R114.2 U8.W5(IO,_RZQ_B_3D,_CDR,_DIFF_RX_3D18P,_DQ53)
FPGA_1V2_AVSTx16_CLK: U8.B44(IO,_DIFF_TX_3A8N,_DQSN90,_AVST_CLK) ; also on sheet 10
FPGA_1V2_AVSTx16_D0: U8.A35(IO,_DIFF_TX_3A12P,_DQ91,_AVST_DATA0) ; also on sheet 10
FPGA_1V2_AVSTx16_D1: U8.B36(IO,_DIFF_TX_3A12N,_DQ91,_AVST_DATA1) ; also on sheet 10
FPGA_1V2_AVSTx16_D2: U8.E35(IO,_CDR,_DIFF_RX_3A12P,_DQ91,_AVST_DATA2) ; also on sheet 10
FPGA_1V2_AVSTx16_D3: U8.D36(IO,_CDR,_DIFF_RX_3A12N,_DQ91,_AVST_DATA3) ; also on sheet 10
FPGA_1V2_AVSTx16_D4: U8.A37(IO,_DIFF_TX_3A11P,_DQS91,_AVST_DATA4) ; also on sheet 10
FPGA_1V2_AVSTx16_D5: U8.B38(IO,_DIFF_TX_3A11N,_DQSN91,_AVST_DATA5) ; also on sheet 10
FPGA_1V2_AVSTx16_D6: U8.E37(IO,_DIFF_RX_3A11P,_DQ91,_AVST_DATA6) ; also on sheet 10
FPGA_1V2_AVSTx16_D7: U8.D38(IO,_DIFF_RX_3A11N,_DQ91,_AVST_DATA7) ; also on sheet 10
FPGA_1V2_AVSTx16_D8: U8.B40(IO,_DIFF_TX_3A10N,_DQ91,_AVST_DATA8) ; also on sheet 10
FPGA_1V2_AVSTx16_D9: U8.E39(IO,_DIFF_RX_3A10P,_DQ91,_AVST_DATA9) ; also on sheet 10
FPGA_1V2_AVSTx16_D10: U8.D40(IO,_DIFF_RX_3A10N,_DQ91,_AVST_DATA10) ; also on sheet 10
FPGA_1V2_AVSTx16_D11: U8.A41(IO,_DIFF_TX_3A9P,_DQ90,_AVST_DATA11) ; also on sheet 10
FPGA_1V2_AVSTx16_D12: U8.B42(IO,_DIFF_TX_3A9N,_DQ90,_AVST_DATA12) ; also on sheet 10
FPGA_1V2_AVSTx16_D13: U8.E41(IO,_CDR,_DIFF_RX_3A9P,_DQ90,_AVST_DATA13) ; also on sheet 10
FPGA_1V2_AVSTx16_D14: U8.D42(IO,_CDR,_DIFF_RX_3A9N,_DQ90,_AVST_DATA14) ; also on sheet 10
FPGA_1V2_AVSTx16_D15: U8.A43(IO,_DIFF_TX_3A8P,_DQS90,_AVST_DATA15) ; also on sheet 10
FPGA_1V2_AVSTx16_READY: U8.E49(IO,_DIFF_RX_3A2P,_DQ88,_AVST_READY) ; also on sheet 10
FPGA_1V2_AVSTx16_VALID: U8.A39(IO,_DIFF_TX_3A10P,_DQ91,_AVST_VALID) ; also on sheet 10
FPGA_1V2_LED0: U8.B50(IO,_DIFF_TX_3A2N,_DQSN88,_AVST_DATA31) ; also on sheet 34
FPGA_1V2_LED1: U8.A49(IO,_DIFF_TX_3A2P,_DQS88,_AVST_DATA30) ; also on sheet 34
FPGA_1V2_LED2: U8.D48(IO,_CDR,_DIFF_RX_3A3N,_DQ88,_AVST_DATA29) ; also on sheet 34
FPGA_1V2_LED3: U8.E47(IO,_CDR,_DIFF_RX_3A3P,_DQ88,_AVST_DATA28) ; also on sheet 34
FPGA_1V2_SCL: U8.K44(IO,_CDR,_DIFF_RX_3A6N,_DQ89,_AVST_DATA17) ; also on sheet 35
FPGA_1V2_SDA: U8.J43(IO,_RZQ_T_3A,_CDR,_DIFF_RX_3A6P,_DQ89,_AVST_DATA16) ; also on sheet 35
FPGA_3V3_SCL: U97.14(SCL) ; also on sheet 29 30 35 37
FPGA_3V3_SDA: U97.15(SDA) ; also on sheet 29 30 35 37
FPGA_CXL_PRSNTx4_N: U8.F50(IO,_DIFF_RX_3A4N,_DQ89,_AVST_DATA25) ; also on sheet 31
FPGA_CXL_RSTn: U8.D44(IO,_PLL_3A_T_CLKOUT0N,_DIFF_RX_3A8N,_DQ90) ; also on sheet 34
FPGA_RCVD_CLK1_REFOUT_N: U8.AE49(REFCLK_FGTL12C_Q2_CH8N) ; also on sheet 32
FPGA_RCVD_CLK1_REFOUT_P: U8.AG49(REFCLK_FGTL12C_Q2_CH8P) ; also on sheet 32
FPGA_RCVD_CLK2_REFOUT_N: U8.V46(REFCLK_FGTL12C_Q3_CH9N) ; also on sheet 32
FPGA_RCVD_CLK2_REFOUT_P: U8.W45(REFCLK_FGTL12C_Q3_CH9P) ; also on sheet 32
FPGA_VCCIO_1V2: R6895.2 R6898.2 ; also on sheet 10 23 25 26 27 31 34 35 36 39 50 54 55 56
GXF_1V2_2ND_PERSTn: U8.B46(IO,_DIFF_TX_3A7N,_DQ90) ; also on sheet 34
IOEXP_INTn: R6895.1 U8.E43(IO,_PLL_3A_T_CLKOUT0P,_PLL_3A_T_CLKOUT0,_PLL_3A_T_FB0,_DIFF_RX_3A8P,_DQ90) U97.13(INT_N)
MAX10_FPGA_RESETn: R6898.1 U8.D54(IO,_DIFF_RX_3A1N,_DQ88) U8.Y42(IO,_CDR,_DIFF_RX_3A13N,_DQ92) ; also on sheet 10
MAX_1V2_FPGA_SPARE0: U8.G47(IO,_DIFF_TX_3A4P,_DQ89,_AVST_DATA22) ; also on sheet 10
MAX_1V2_FPGA_SPARE1: U8.K46(IO,_DIFF_RX_3A5N,_DQ89,_AVST_DATA21) ; also on sheet 10
MAX_1V2_FPGA_SPARE2: U8.J45(IO,_DIFF_RX_3A5P,_DQ89,_AVST_DATA20) ; also on sheet 10
MAX_1V2_FPGA_SPARE3: U8.F46(IO,_PLL_3A_T_CLKOUT1N,_DIFF_TX_3A5N,_DQSN89,_AVST_DATA19) ; also on sheet 10
PCIE_EP_RX_N0: U8.AL5(FGTR13A_TX_Q0_CH0N) ; also on sheet 8
PCIE_EP_RX_N1: U8.AM8(FGTR13A_TX_Q0_CH1N) ; also on sheet 8
PCIE_EP_RX_N2: U8.AR5(FGTR13A_TX_Q0_CH2N) ; also on sheet 8
PCIE_EP_RX_N3: U8.AT8(FGTR13A_TX_Q0_CH3N) ; also on sheet 8
PCIE_EP_RX_N4: U8.AW5(FGTR13A_TX_Q1_CH0N) ; also on sheet 8
PCIE_EP_RX_N5: U8.AY8(FGTR13A_TX_Q1_CH1N) ; also on sheet 8
PCIE_EP_RX_N6: U8.BC5(FGTR13A_TX_Q1_CH2N) ; also on sheet 8
PCIE_EP_RX_N7: U8.BG5(FGTR13A_TX_Q1_CH3N) ; also on sheet 8
PCIE_EP_RX_N8: U8.BL5(FGTR13A_TX_Q2_CH0N) ; also on sheet 8
PCIE_EP_RX_N9: U8.BR5(FGTR13A_TX_Q2_CH1N) ; also on sheet 8
PCIE_EP_RX_N10: U8.BW5(FGTR13A_TX_Q2_CH2N) ; also on sheet 8
PCIE_EP_RX_N11: U8.CC5(FGTR13A_TX_Q2_CH3N) ; also on sheet 8
PCIE_EP_RX_N12: U8.CG5(FGTR13A_TX_Q3_CH0N) ; also on sheet 8
PCIE_EP_RX_N13: U8.CL5(FGTR13A_TX_Q3_CH1N) ; also on sheet 8
PCIE_EP_RX_N14: U8.CM8(FGTR13A_TX_Q3_CH2N) ; also on sheet 8
PCIE_EP_RX_N15: U8.CT8(FGTR13A_TX_Q3_CH3N) ; also on sheet 8
PCIE_EP_RX_P0: U8.AK4(FGTR13A_TX_Q0_CH0P) ; also on sheet 8
PCIE_EP_RX_P1: U8.AN7(FGTR13A_TX_Q0_CH1P) ; also on sheet 8
PCIE_EP_RX_P2: U8.AP4(FGTR13A_TX_Q0_CH2P) ; also on sheet 8
PCIE_EP_RX_P3: U8.AU7(FGTR13A_TX_Q0_CH3P) ; also on sheet 8
PCIE_EP_RX_P4: U8.AV4(FGTR13A_TX_Q1_CH0P) ; also on sheet 8
PCIE_EP_RX_P5: U8.BA7(FGTR13A_TX_Q1_CH1P) ; also on sheet 8
PCIE_EP_RX_P6: U8.BB4(FGTR13A_TX_Q1_CH2P) ; also on sheet 8
PCIE_EP_RX_P7: U8.BF4(FGTR13A_TX_Q1_CH3P) ; also on sheet 8
PCIE_EP_RX_P8: U8.BK4(FGTR13A_TX_Q2_CH0P) ; also on sheet 8
PCIE_EP_RX_P9: U8.BP4(FGTR13A_TX_Q2_CH1P) ; also on sheet 8
PCIE_EP_RX_P10: U8.BV4(FGTR13A_TX_Q2_CH2P) ; also on sheet 8
PCIE_EP_RX_P11: U8.CB4(FGTR13A_TX_Q2_CH3P) ; also on sheet 8
PCIE_EP_RX_P12: U8.CF4(FGTR13A_TX_Q3_CH0P) ; also on sheet 8
PCIE_EP_RX_P13: U8.CK4(FGTR13A_TX_Q3_CH1P) ; also on sheet 8
PCIE_EP_RX_P14: U8.CN7(FGTR13A_TX_Q3_CH2P) ; also on sheet 8
PCIE_EP_RX_P15: U8.CU7(FGTR13A_TX_Q3_CH3P) ; also on sheet 8
PCIE_EP_TX_N0: U8.AG5(FGTR13A_RX_Q0_CH0N) ; also on sheet 8
PCIE_EP_TX_N1: U8.AH2(FGTR13A_RX_Q0_CH1N) ; also on sheet 8
PCIE_EP_TX_N2: U8.AM2(FGTR13A_RX_Q0_CH2N) ; also on sheet 8
PCIE_EP_TX_N3: U8.AT2(FGTR13A_RX_Q0_CH3N) ; also on sheet 8
PCIE_EP_TX_N4: U8.AY2(FGTR13A_RX_Q1_CH0N) ; also on sheet 8
PCIE_EP_TX_N5: U8.BD2(FGTR13A_RX_Q1_CH1N) ; also on sheet 8
PCIE_EP_TX_N6: U8.BH2(FGTR13A_RX_Q1_CH2N) ; also on sheet 8
PCIE_EP_TX_N7: U8.BM2(FGTR13A_RX_Q1_CH3N) ; also on sheet 8
PCIE_EP_TX_N8: U8.BT2(FGTR13A_RX_Q2_CH0N) ; also on sheet 8
PCIE_EP_TX_N9: U8.BY2(FGTR13A_RX_Q2_CH1N) ; also on sheet 8
PCIE_EP_TX_N10: U8.CD2(FGTR13A_RX_Q2_CH2N) ; also on sheet 8
PCIE_EP_TX_N11: U8.CH2(FGTR13A_RX_Q2_CH3N) ; also on sheet 8
PCIE_EP_TX_N12: U8.CM2(FGTR13A_RX_Q3_CH0N) ; also on sheet 8
PCIE_EP_TX_N13: U8.CR5(FGTR13A_RX_Q3_CH1N) ; also on sheet 8
PCIE_EP_TX_N14: U8.CT2(FGTR13A_RX_Q3_CH2N) ; also on sheet 8
PCIE_EP_TX_N15: U8.CW5(FGTR13A_RX_Q3_CH3N) ; also on sheet 8
PCIE_EP_TX_P0: U8.AF4(FGTR13A_RX_Q0_CH0P) ; also on sheet 8
PCIE_EP_TX_P1: U8.AJ1(FGTR13A_RX_Q0_CH1P) ; also on sheet 8
PCIE_EP_TX_P2: U8.AN1(FGTR13A_RX_Q0_CH2P) ; also on sheet 8
PCIE_EP_TX_P3: U8.AU1(FGTR13A_RX_Q0_CH3P) ; also on sheet 8
PCIE_EP_TX_P4: U8.BA1(FGTR13A_RX_Q1_CH0P) ; also on sheet 8
PCIE_EP_TX_P5: U8.BE1(FGTR13A_RX_Q1_CH1P) ; also on sheet 8
PCIE_EP_TX_P6: U8.BJ1(FGTR13A_RX_Q1_CH2P) ; also on sheet 8
PCIE_EP_TX_P7: U8.BN1(FGTR13A_RX_Q1_CH3P) ; also on sheet 8
PCIE_EP_TX_P8: U8.BU1(FGTR13A_RX_Q2_CH0P) ; also on sheet 8
PCIE_EP_TX_P9: U8.CA1(FGTR13A_RX_Q2_CH1P) ; also on sheet 8
PCIE_EP_TX_P10: U8.CE1(FGTR13A_RX_Q2_CH2P) ; also on sheet 8
PCIE_EP_TX_P11: U8.CJ1(FGTR13A_RX_Q2_CH3P) ; also on sheet 8
PCIE_EP_TX_P12: U8.CN1(FGTR13A_RX_Q3_CH0P) ; also on sheet 8
PCIE_EP_TX_P13: U8.CP4(FGTR13A_RX_Q3_CH1P) ; also on sheet 8
PCIE_EP_TX_P14: U8.CU1(FGTR13A_RX_Q3_CH2P) ; also on sheet 8
PCIE_EP_TX_P15: U8.CV4(FGTR13A_RX_Q3_CH3P) ; also on sheet 8
PPS_FPGA_CLKOUT: R845.2 ; also on sheet 32
PTP_SAMPLE_CLK_250M_N: R6911.2 R6937.1 U8.D46(IO,_CLK_T_3A_0N,_DIFF_RX_3A7N,_DQ90) ; also on sheet 32
PTP_SAMPLE_CLK_250M_P: R6911.1 R6936.1 U8.E45(IO,_CLK_T_3A_0P,_DIFF_RX_3A7P,_DQ90) ; also on sheet 32
QSFP_1V2_LED1: U8.B48(IO,_DIFF_TX_3A3N,_DQ88,_AVST_DATA27) ; also on sheet 36
QSFP_1V2_LED2: U8.A47(IO,_DIFF_TX_3A3P,_DQ88,_AVST_DATA26) ; also on sheet 36
QSFP_3V3_INT_L: U97.5(P1) ; also on sheet 29 30
QSFP_3V3_LPMODE: U97.6(P2) ; also on sheet 30
QSFP_3V3_MODPRS_L: U97.9(P4) ; also on sheet 10 30
QSFP_3V3_RESET_L: U97.4(P0) ; also on sheet 29 30
QSFP_3V3_SELn: U97.12(P7) ; also on sheet 30
QSFP_REFCLK_N: R6915.2 R6926.1 U8.AV48(REFCLK_FGTL12C_Q1_RX_CH2N) ; also on sheet 32
QSFP_REFCLK_P: R6915.1 R6925.1 U8.AW49(REFCLK_FGTL12C_Q1_RX_CH2P) ; also on sheet 32
QSFP_RX0_N: U8.BM54(FGTL12C_RX_Q1_CH0N) ; also on sheet 30
QSFP_RX0_P: U8.BL55(FGTL12C_RX_Q1_CH0P) ; also on sheet 30
QSFP_RX1_N: U8.AY54(FGTL12C_RX_Q1_CH3N) ; also on sheet 30
QSFP_RX1_P: U8.AW55(FGTL12C_RX_Q1_CH3P) ; also on sheet 30
QSFP_RX2_N: U8.BG55(FGTL12C_RX_Q1_CH1P) ; also on sheet 30
QSFP_RX2_P: U8.BH54(FGTL12C_RX_Q1_CH1N) ; also on sheet 30
QSFP_RX3_N: U8.BD54(FGTL12C_RX_Q1_CH2N) ; also on sheet 30
QSFP_RX3_P: U8.BC55(FGTL12C_RX_Q1_CH2P) ; also on sheet 30
QSFP_TX0_N: U8.BM48(FGTL12C_TX_Q1_CH0N) ; also on sheet 30
QSFP_TX0_P: U8.BL49(FGTL12C_TX_Q1_CH0P) ; also on sheet 30
QSFP_TX1_N: U8.BA51(FGTL12C_TX_Q1_CH3N) ; also on sheet 30
QSFP_TX1_P: U8.BB52(FGTL12C_TX_Q1_CH3P) ; also on sheet 30
QSFP_TX2_N: U8.BK52(FGTL12C_TX_Q1_CH1P) ; also on sheet 30
QSFP_TX2_P: U8.BJ51(FGTL12C_TX_Q1_CH1N) ; also on sheet 30
QSFP_TX3_N: U8.BF52(FGTL12C_TX_Q1_CH2P) ; also on sheet 30
QSFP_TX3_P: U8.BE51(FGTL12C_TX_Q1_CH2N) ; also on sheet 30
QSFPDD_1V2_LED1: U8.G49(IO,_DIFF_RX_3A4P,_DQ89,_AVST_DATA24) ; also on sheet 36
QSFPDD_1V2_LED2: U8.F48(IO,_DIFF_TX_3A4N,_DQ89,_AVST_DATA23) ; also on sheet 36
QSFPDD_3V3_LPMODE: U97.7(P3) ; also on sheet 29
QSFPDD_3V3_MODPRS_L: U97.10(P5) ; also on sheet 10 29
QSFPDD_3V3_SELn: U97.11(P6) ; also on sheet 29
QSFPDD_REFCLK_N: R6914.1 R6924.2 U8.AC49(REFCLK_FGTL12C_Q3_RX_CH6N) ; also on sheet 32
QSFPDD_REFCLK_P: R6914.2 R6923.2 U8.AD48(REFCLK_FGTL12C_Q3_RX_CH6P) ; also on sheet 32
QSFPDD_RX0_N: U8.AT54(FGTL12C_RX_Q2_CH0N) ; also on sheet 29
QSFPDD_RX0_P: U8.AR55(FGTL12C_RX_Q2_CH0P) ; also on sheet 29
QSFPDD_RX1_N: U8.J51(FGTL12C_RX_Q3_CH3N) ; also on sheet 29
QSFPDD_RX1_P: U8.K52(FGTL12C_RX_Q3_CH3P) ; also on sheet 29
QSFPDD_RX2_N: U8.AM54(FGTL12C_RX_Q2_CH1N) ; also on sheet 29
QSFPDD_RX2_P: U8.AL55(FGTL12C_RX_Q2_CH1P) ; also on sheet 29
QSFPDD_RX3_N: U8.N51(FGTL12C_RX_Q3_CH2N) ; also on sheet 29
QSFPDD_RX3_P: U8.P52(FGTL12C_RX_Q3_CH2P) ; also on sheet 29
QSFPDD_RX4_N: U8.AD54(FGTL12C_RX_Q2_CH3N) ; also on sheet 29
QSFPDD_RX4_P: U8.AC55(FGTL12C_RX_Q2_CH3P) ; also on sheet 29
QSFPDD_RX5_N: U8.T54(FGTL12C_RX_Q3_CH1N) ; also on sheet 29
QSFPDD_RX5_P: U8.R55(FGTL12C_RX_Q3_CH1P) ; also on sheet 29
QSFPDD_RX6_N: U8.AH54(FGTL12C_RX_Q2_CH2N) ; also on sheet 29
QSFPDD_RX6_P: U8.AG55(FGTL12C_RX_Q2_CH2P) ; also on sheet 29
QSFPDD_RX7_N: U8.Y54(FGTL12C_RX_Q3_CH0N) ; also on sheet 29
QSFPDD_RX7_P: U8.W55(FGTL12C_RX_Q3_CH0P) ; also on sheet 29
QSFPDD_TX0_N: U8.AU51(FGTL12C_TX_Q2_CH0N) ; also on sheet 29
QSFPDD_TX0_P: U8.AV52(FGTL12C_TX_Q2_CH0P) ; also on sheet 29
QSFPDD_TX1_N: U8.T48(FGTL12C_TX_Q3_CH3N) ; also on sheet 29
QSFPDD_TX1_P: U8.R49(FGTL12C_TX_Q3_CH3P) ; also on sheet 29
QSFPDD_TX2_N: U8.AP52(FGTL12C_TX_Q2_CH1P) ; also on sheet 29
QSFPDD_TX2_P: U8.AN51(FGTL12C_TX_Q2_CH1N) ; also on sheet 29
QSFPDD_TX3_N: U8.V52(FGTL12C_TX_Q3_CH2P) ; also on sheet 29
QSFPDD_TX3_P: U8.U51(FGTL12C_TX_Q3_CH2N) ; also on sheet 29
QSFPDD_TX4_N: U8.AE51(FGTL12C_TX_Q2_CH3N) ; also on sheet 29
QSFPDD_TX4_P: U8.AF52(FGTL12C_TX_Q2_CH3P) ; also on sheet 29
QSFPDD_TX5_N: U8.W49(FGTL12C_TX_Q3_CH1P) ; also on sheet 29
QSFPDD_TX5_P: U8.Y48(FGTL12C_TX_Q3_CH1N) ; also on sheet 29
QSFPDD_TX6_N: U8.AK52(FGTL12C_TX_Q2_CH2P) ; also on sheet 29
QSFPDD_TX6_P: U8.AJ51(FGTL12C_TX_Q2_CH2N) ; also on sheet 29
QSFPDD_TX7_N: U8.AB52(FGTL12C_TX_Q3_CH0P) ; also on sheet 29
QSFPDD_TX7_P: U8.AA51(FGTL12C_TX_Q3_CH0N) ; also on sheet 29
REFCLK_CXL_CONN_N: R758.1 R6920.2 U8.BF48(REFCLK_FGTL12C_Q0_RX_CH1N) ; also on sheet 33
REFCLK_CXL_CONN_P: R757.1 R6920.1 U8.BG49(REFCLK_FGTL12C_Q0_RX_CH1P) ; also on sheet 33
REFCLK_CXL_EP_N: R756.1 R6919.2 U8.BE49(REFCLK_FGTL12C_Q0_RX_CH0N) ; also on sheet 33
REFCLK_CXL_EP_P: R755.1 R6919.1 U8.BC49(REFCLK_FGTL12C_Q0_RX_CH0P) ; also on sheet 33
REFCLK_PCIE_13A_CH2_N: R118.1 R6918.2 U8.BU7(REFCLK_FGTR13A_Q1_RX_CH2N) ; also on sheet 33
REFCLK_PCIE_13A_CH2_P: R117.1 R6918.1 U8.BR7(REFCLK_FGTR13A_Q1_RX_CH2P) ; also on sheet 33
REFCLK_PCIE_13A_CH5_N: R115.2 R6917.1 U8.CC7(REFCLK_FGTR13A_Q2_RX_CH5N) ; also on sheet 33
REFCLK_PCIE_13A_CH5_P: R116.2 R6917.2 U8.CD8(REFCLK_FGTR13A_Q2_RX_CH5P) ; also on sheet 33
ToD_MASTER_CLK_125M_N: R6910.2 R6935.1 U8.F44(IO,_CLK_T_3A_1N,_DIFF_TX_3A6N,_DQ89) ; also on sheet 32
ToD_MASTER_CLK_125M_P: R6910.1 R6934.1 U8.G43(IO,_CLK_T_3A_1P,_DIFF_TX_3A6P,_DQ89) ; also on sheet 32
N4269052: U8.J47(IO,_DIFF_TX_3A16P,_DQ93) U8.K48(IO,_DIFF_TX_3A16N,_DQ93)
N6060143: R845.1 U8.G45(IO,_PLL_3A_T_CLKOUT1P,_PLL_3A_T_CLKOUT1,_PLL_3A_T_FB1,_DIFF_TX_3A5P,_DQS89,_AVST_DATA18)
N7393705: R6893.1 U97.1(A0)
N7393712: R6892.1 U97.2(A1)
N7393719: R6891.1 U97.3(A2)

Not connected (* = marked no-connect by the designer): U8 A11(IO,_DIFF_TX_3C1P,_DQ56)* A13(IO,_DIFF_TX_3C2P,_DQS56)* A15(IO,_DIFF_TX_3C3P,_DQ56)* A17(IO,_DIFF_TX_3C7P,_DQ58)* A19(IO,_DIFF_TX_3C8P,_DQS58)* A21(IO,_DIFF_TX_3C9P,_DQ58)* A23(IO,_DIFF_TX_3B12P,_DQ83)* A25(IO,_DIFF_TX_3B11P,_DQS83)* A27(IO,_DIFF_TX_3B10P,_DQ83)* A29(IO,_CLK_T_3B_1P,_DIFF_TX_3B6P,_DQ81)* A31(IO,_PLL_3B_T_CLKOUT1P,_PLL_3B_T_CLKOUT1,_PLL_3B_T_FB1,_DIFF_TX_3B5P,_DQS81)* A33(IO,_DIFF_TX_3B4P,_DQ81)* AB4(IO,_DIFF_RX_3D14N,_DQ52)* B12(IO,_DIFF_TX_3C1N,_DQ56)* B14(IO,_DIFF_TX_3C2N,_DQSN56)* B16(IO,_DIFF_TX_3C3N,_DQ56)* B18(IO,_DIFF_TX_3C7N,_DQ58)* B20(IO,_DIFF_TX_3C8N,_DQSN58)* B22(IO,_DIFF_TX_3C9N,_DQ58)* B24(IO,_DIFF_TX_3B12N,_DQ83)* B26(IO,_DIFF_TX_3B11N,_DQSN83)* B28(IO,_DIFF_TX_3B10N,_DQ83)* B30(IO,_CLK_T_3B_1N,_DIFF_TX_3B6N,_DQ81)* B32(IO,_PLL_3B_T_CLKOUT1N,_DIFF_TX_3B5N,_DQSN81)* B34(IO,_DIFF_TX_3B4N,_DQ81)* CE7(REFCLK_FGTR13A_Q2_CH8P)* CG7(REFCLK_FGTR13A_Q2_CH8N)* CG11(REFCLK_FGTR13A_Q3_CH9N)* CH10(REFCLK_FGTR13A_Q3_CH9P)* D8(IO,_PLL_3D_T_CLKOUT0N,_DIFF_RX_3D8N,_DQ50)* D12(IO,_DIFF_RX_3C1N,_DQ56)* D14(IO,_DIFF_RX_3C2N,_DQ56)* D16(IO,_CDR,_DIFF_RX_3C3N,_DQ56)* D18(IO,_CLK_T_3C_0N,_DIFF_RX_3C7N,_DQ58)* D20(IO,_PLL_3C_T_CLKOUT0N,_DIFF_RX_3C8N,_DQ58)* D22(IO,_CDR,_DIFF_RX_3C9N,_DQ58)* D24(IO,_CDR,_DIFF_RX_3B12N,_DQ83)* D26(IO,_DIFF_RX_3B11N,_DQ83)* D28(IO,_DIFF_RX_3B10N,_DQ83)* D30(IO,_CDR,_DIFF_RX_3B6N,_DQ81)* D32(IO,_DIFF_RX_3B5N,_DQ81)* D34(IO,_DIFF_RX_3B4N,_DQ81)* D50(IO,_DIFF_RX_3A2N,_DQ88)* D52(IO,_DIFF_TX_3A1N,_DQ88)* E11(IO,_DIFF_RX_3C1P,_DQ56)* E13(IO,_DIFF_RX_3C2P,_DQ56)* E15(IO,_CDR,_DIFF_RX_3C3P,_DQ56)* E17(IO,_CLK_T_3C_0P,_DIFF_RX_3C7P,_DQ58)* E19(IO,_PLL_3C_T_CLKOUT0P,_PLL_3C_T_CLKOUT0,_PLL_3C_T_FB0,_DIFF_RX_3C8P,_DQ58)* E21(IO,_CDR,_DIFF_RX_3C9P,_DQ58)* E23(IO,_CDR,_DIFF_RX_3B12P,_DQ83)* E25(IO,_DIFF_RX_3B11P,_DQ83)* E27(IO,_DIFF_RX_3B10P,_DQ83)* E29(IO,_RZQ_T_3B,_CDR,_DIFF_RX_3B6P,_DQ81)* E31(IO,_DIFF_RX_3B5P,_DQ81)* E33(IO,_DIFF_RX_3B4P,_DQ81)* E51(IO,_DIFF_TX_3A1P,_DQ88)* E53(IO,_DIFF_RX_3A1P,_DQ88)* F14(IO,_DIFF_TX_3C4N,_DQ57)* F16(IO,_PLL_3C_T_CLKOUT1N,_DIFF_TX_3C5N,_DQSN57)* F18(IO,_CLK_T_3C_1N,_DIFF_TX_3C6N,_DQ57)* F20(IO,_DIFF_TX_3C10N,_DQ59)* F22(IO,_DIFF_TX_3C11N,_DQSN59)* F24(IO,_DIFF_TX_3C12N,_DQ59)* F26(IO,_DIFF_TX_3B9N,_DQ82)* F28(IO,_DIFF_TX_3B8N,_DQSN82)* F30(IO,_DIFF_TX_3B7N,_DQ82)* F32(IO,_DIFF_TX_3B3N,_DQ80)* F34(IO,_DIFF_TX_3B2N,_DQSN80)* F36(IO,_DIFF_TX_3B1N,_DQ80)* F38(IO,_DIFF_TX_3A24N,_DQ95)* F40(IO,_DIFF_TX_3A23N,_DQSN95)* F42(IO,_DIFF_TX_3A22N,_DQ95)* G13(IO,_DIFF_TX_3C4P,_DQ57)* G15(IO,_PLL_3C_T_CLKOUT1P,_PLL_3C_T_CLKOUT1,_PLL_3C_T_FB1,_DIFF_TX_3C5P,_DQS57)* G17(IO,_CLK_T_3C_1P,_DIFF_TX_3C6P,_DQ57)* G19(IO,_DIFF_TX_3C10P,_DQ59)* G21(IO,_DIFF_TX_3C11P,_DQS59)* G23(IO,_DIFF_TX_3C12P,_DQ59)* G25(IO,_DIFF_TX_3B9P,_DQ82)* G27(IO,_DIFF_TX_3B8P,_DQS82)* G29(IO,_DIFF_TX_3B7P,_DQ82)* G31(IO,_DIFF_TX_3B3P,_DQ80)* G33(IO,_DIFF_TX_3B2P,_DQS80)* G35(IO,_DIFF_TX_3B1P,_DQ80)* G37(IO,_DIFF_TX_3A24P,_DQ95)* G39(IO,_DIFF_TX_3A23P,_DQS95)* G41(IO,_DIFF_TX_3A22P,_DQ95)* J13(IO,_DIFF_RX_3C4P,_DQ57)* J15(IO,_DIFF_RX_3C5P,_DQ57)* J17(IO,_RZQ_T_3C,_CDR,_DIFF_RX_3C6P,_DQ57)* J19(IO,_DIFF_RX_3C10P,_DQ59)* J21(IO,_DIFF_RX_3C11P,_DQ59)* J23(IO,_CDR,_DIFF_RX_3C12P,_DQ59)* J25(IO,_CDR,_DIFF_RX_3B9P,_DQ82)* J27(IO,_PLL_3B_T_CLKOUT0P,_PLL_3B_T_CLKOUT0,_PLL_3B_T_FB0,_DIFF_RX_3B8P,_DQ82)* J29(IO,_CLK_T_3B_0P,_DIFF_RX_3B7P,_DQ82)* J31(IO,_CDR,_DIFF_RX_3B3P,_DQ80)* J33(IO,_DIFF_RX_3B2P,_DQ80)* J35(IO,_DIFF_RX_3B1P,_DQ80)* J37(IO,_CDR,_DIFF_RX_3A24P,_DQ95)* J39(IO,_DIFF_RX_3A23P,_DQ95)* J41(IO,_CDR,_DIFF_RX_3A22P,_DQ95)* K4(IO,_DIFF_RX_3D5N,_DQ49)* K10(IO,_DIFF_RX_3D11N,_DQ51)* K14(IO,_DIFF_RX_3C4N,_DQ57)* K16(IO,_DIFF_RX_3C5N,_DQ57)* K18(IO,_CDR,_DIFF_RX_3C6N,_DQ57)* K20(IO,_DIFF_RX_3C10N,_DQ59)* K22(IO,_DIFF_RX_3C11N,_DQ59)* K24(IO,_CDR,_DIFF_RX_3C12N,_DQ59)* K26(IO,_CDR,_DIFF_RX_3B9N,_DQ82)* K28(IO,_PLL_3B_T_CLKOUT0N,_DIFF_RX_3B8N,_DQ82)* K30(IO,_CLK_T_3B_0N,_DIFF_RX_3B7N,_DQ82)* K32(IO,_CDR,_DIFF_RX_3B3N,_DQ80)* K34(IO,_DIFF_RX_3B2N,_DQ80)* K36(IO,_DIFF_RX_3B1N,_DQ80)* K38(IO,_CDR,_DIFF_RX_3A24N,_DQ95)* K40(IO,_DIFF_RX_3A23N,_DQ95)* K42(IO,_CDR,_DIFF_RX_3A22N,_DQ95)* L13(IO,_DIFF_TX_3C16P,_DQ61)* L15(IO,_PLL_3C_B_CLKOUT1P,_PLL_3C_B_CLKOUT1,_PLL_3C_B_FB1,_DIFF_TX_3C17P,_DQS61)* L17(IO,_CLK_B_3C_1P,_DIFF_TX_3C18P,_DQ61)* L19(IO,_DIFF_TX_3C19P,_DQ62)* L21(IO,_DIFF_TX_3C20P,_DQS62)* L23(IO,_DIFF_TX_3C21P,_DQ62)* L25(IO,_DIFF_TX_3B21P,_DQ86)* L27(IO,_DIFF_TX_3B20P,_DQS86)* L29(IO,_DIFF_TX_3B19P,_DQ86)* L31(IO,_DIFF_TX_3B15P,_DQ84)* L33(IO,_DIFF_TX_3B14P,_DQS84)* L35(IO,_DIFF_TX_3B13P,_DQ84)* L37(IO,_DIFF_TX_3A21P,_DQ94)* L39(IO,_DIFF_TX_3A20P,_DQS94)* L41(IO,_DIFF_TX_3A19P,_DQ94)* L43(IO,_CLK_B_3A_1P,_DIFF_TX_3A18P,_DQ93)* L45(IO,_PLL_3A_B_CLKOUT1P,_PLL_3A_B_CLKOUT1,_PLL_3A_B_FB1,_DIFF_TX_3A17P,_DQS93)* L47(IO,_CDR,_DIFF_RX_3A16P,_DQ93)* M10(IO,_DIFF_TX_3D23N,_DQSN55)* M14(IO,_DIFF_TX_3C16N,_DQ61)* M16(IO,_PLL_3C_B_CLKOUT1N,_DIFF_TX_3C17N,_DQSN61)* M18(IO,_CLK_B_3C_1N,_DIFF_TX_3C18N,_DQ61)* M20(IO,_DIFF_TX_3C19N,_DQ62)* M22(IO,_DIFF_TX_3C20N,_DQSN62)* M24(IO,_DIFF_TX_3C21N,_DQ62)* M26(IO,_DIFF_TX_3B21N,_DQ86)* M28(IO,_DIFF_TX_3B20N,_DQSN86)* M30(IO,_DIFF_TX_3B19N,_DQ86)* M32(IO,_DIFF_TX_3B15N,_DQ84)* M34(IO,_DIFF_TX_3B14N,_DQSN84)* M36(IO,_DIFF_TX_3B13N,_DQ84)* M40(IO,_DIFF_TX_3A20N,_DQSN94)* M42(IO,_DIFF_TX_3A19N,_DQ94)* M44(IO,_CLK_B_3A_1N,_DIFF_TX_3A18N,_DQ93)* M46(IO,_PLL_3A_B_CLKOUT1N,_DIFF_TX_3A17N,_DQSN93)* M48(IO,_CDR,_DIFF_RX_3A16N,_DQ93)* P4(IO,_DIFF_RX_3D2N,_DQ48)* P10(IO,_DIFF_RX_3D23N,_DQ55)* P14(IO,_CDR,_DIFF_RX_3C16N,_DQ61)* P16(IO,_DIFF_RX_3C17N,_DQ61)* P18(IO,_CDR,_DIFF_RX_3C18N,_DQ61)* P20(IO,_CLK_B_3C_0N,_CDR,_DIFF_RX_3C19N,_DQ62)* P22(IO,_PLL_3C_B_CLKOUT0N,_DIFF_RX_3C20N,_DQ62)* P24(IO,_CDR,_DIFF_RX_3C21N,_DQ62)* P26(IO,_CDR,_DIFF_RX_3B21N,_DQ86)* P28(IO,_PLL_3B_B_CLKOUT0N,_DIFF_RX_3B20N,_DQ86)* P30(IO,_CLK_B_3B_0N,_CDR,_DIFF_RX_3B19N,_DQ86)* P32(IO,_CDR,_DIFF_RX_3B15N,_DQ84)* P34(IO,_DIFF_RX_3B14N,_DQ84)* P36(IO,_CDR,_DIFF_RX_3B13N,_DQ84)* P38(IO,_CDR,_DIFF_RX_3A21N,_DQ94)* P40(IO,_PLL_3A_B_CLKOUT0N,_DIFF_RX_3A20N,_DQ94)* P42(IO,_CLK_B_3A_0N,_CDR,_DIFF_RX_3A19N,_DQ94)* P44(IO,_CDR,_DIFF_RX_3A18N,_DQ93)* P46(IO,_DIFF_RX_3A17N,_DQ93)* R7(IO,_CDR,_DIFF_RX_3D22P,_DQ55)* R13(IO,_CDR,_DIFF_RX_3C16P,_DQ61)* R15(IO,_DIFF_RX_3C17P,_DQ61)* R17(IO,_RZQ_B_3C,_CDR,_DIFF_RX_3C18P,_DQ61)* R19(IO,_CLK_B_3C_0P,_CDR,_DIFF_RX_3C19P,_DQ62)* R21(IO,_PLL_3C_B_CLKOUT0P,_PLL_3C_B_CLKOUT0,_PLL_3C_B_FB0,_DIFF_RX_3C20P,_DQ62)* R23(IO,_CDR,_DIFF_RX_3C21P,_DQ62)* R25(IO,_CDR,_DIFF_RX_3B21P,_DQ86)* R27(IO,_PLL_3B_B_CLKOUT0P,_PLL_3B_B_CLKOUT0,_PLL_3B_B_FB0,_DIFF_RX_3B20P,_DQ86)* R29(IO,_CLK_B_3B_0P,_CDR,_DIFF_RX_3B19P,_DQ86)* R31(IO,_CDR,_DIFF_RX_3B15P,_DQ84)* R33(IO,_DIFF_RX_3B14P,_DQ84)* R35(IO,_CDR,_DIFF_RX_3B13P,_DQ84)* R37(IO,_CDR,_DIFF_RX_3A21P,_DQ94)* R39(IO,_PLL_3A_B_CLKOUT0P,_PLL_3A_B_CLKOUT0,_PLL_3A_B_FB0,_DIFF_RX_3A20P,_DQ94)* R41(IO,_CLK_B_3A_0P,_CDR,_DIFF_RX_3A19P,_DQ94)* R43(IO,_RZQ_B_3A,_CDR,_DIFF_RX_3A18P,_DQ93)* R45(IO,_DIFF_RX_3A17P,_DQ93)* T14(IO,_DIFF_TX_3C13N,_DQ60)* T16(IO,_DIFF_TX_3C14N,_DQSN60)* T18(IO,_DIFF_TX_3C15N,_DQ60)* T20(IO,_DIFF_TX_3C22N,_DQ63)* T22(IO,_DIFF_TX_3C23N,_DQSN63)* T24(IO,_DIFF_TX_3C24N,_DQ63)* T26(IO,_DIFF_TX_3B24N,_DQ87)* T28(IO,_DIFF_TX_3B23N,_DQSN87)* T30(IO,_DIFF_TX_3B22N,_DQ87)* T32(IO,_CLK_B_3B_1N,_DIFF_TX_3B18N,_DQ85)* T34(IO,_PLL_3B_B_CLKOUT1N,_DIFF_TX_3B17N,_DQSN85)* T36(IO,_DIFF_TX_3B16N,_DQ85)* T38(IO,_DIFF_TX_3A15N,_DQ92)* T40(IO,_DIFF_TX_3A14N,_DQSN92)* T42(IO,_DIFF_TX_3A13N,_DQ92)* U13(IO,_DIFF_TX_3C13P,_DQ60)* U15(IO,_DIFF_TX_3C14P,_DQS60)* U17(IO,_DIFF_TX_3C15P,_DQ60)* U19(IO,_DIFF_TX_3C22P,_DQ63)* U21(IO,_DIFF_TX_3C23P,_DQS63)* U23(IO,_DIFF_TX_3C24P,_DQ63)* U25(IO,_DIFF_TX_3B24P,_DQ87)* U27(IO,_DIFF_TX_3B23P,_DQS87)* U29(IO,_DIFF_TX_3B22P,_DQ87)* U31(IO,_CLK_B_3B_1P,_DIFF_TX_3B18P,_DQ85)* U33(IO,_PLL_3B_B_CLKOUT1P,_PLL_3B_B_CLKOUT1,_PLL_3B_B_FB1,_DIFF_TX_3B17P,_DQS85)* U35(IO,_DIFF_TX_3B16P,_DQ85)* U39(IO,_DIFF_TX_3A14P,_DQS92)* U41(IO,_DIFF_TX_3A13P,_DQ92)* W13(IO,_CDR,_DIFF_RX_3C13P,_DQ60)* W15(IO,_DIFF_RX_3C14P,_DQ60)* W17(IO,_CDR,_DIFF_RX_3C15P,_DQ60)* W19(IO,_CDR,_DIFF_RX_3C22P,_DQ63)* W21(IO,_DIFF_RX_3C23P,_DQ63)* W23(IO,_CDR,_DIFF_RX_3C24P,_DQ63)* W25(IO,_CDR,_DIFF_RX_3B24P,_DQ87)* W27(IO,_DIFF_RX_3B23P,_DQ87)* W29(IO,_CDR,_DIFF_RX_3B22P,_DQ87)* W31(IO,_RZQ_B_3B,_CDR,_DIFF_RX_3B18P,_DQ85)* W33(IO,_DIFF_RX_3B17P,_DQ85)* W35(IO,_CDR,_DIFF_RX_3B16P,_DQ85)* W37(IO,_CDR,_DIFF_RX_3A15P,_DQ92)* W39(IO,_DIFF_RX_3A14P,_DQ92)* W41(IO,_CDR,_DIFF_RX_3A13P,_DQ92)* Y14(IO,_CDR,_DIFF_RX_3C13N,_DQ60)* Y16(IO,_DIFF_RX_3C14N,_DQ60)* Y18(IO,_CDR,_DIFF_RX_3C15N,_DQ60)* Y20(IO,_CDR,_DIFF_RX_3C22N,_DQ63)* Y22(IO,_DIFF_RX_3C23N,_DQ63)* Y24(IO,_CDR,_DIFF_RX_3C24N,_DQ63)* Y26(IO,_CDR,_DIFF_RX_3B24N,_DQ87)* Y28(IO,_DIFF_RX_3B23N,_DQ87)* Y30(IO,_CDR,_DIFF_RX_3B22N,_DQ87)* Y32(IO,_CDR,_DIFF_RX_3B18N,_DQ85)* Y34(IO,_DIFF_RX_3B17N,_DQ85)* Y36(IO,_CDR,_DIFF_RX_3B16N,_DQ85)* Y38(IO,_CDR,_DIFF_RX_3A15N,_DQ92)* Y40(IO,_DIFF_RX_3A14N,_DQ92)*

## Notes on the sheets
sheet 16
- This is used for MAX10 to INTERRUPT FPGA
  MUST use ASx4 Configuration Mode.
- FM76 pin D54: MAX10_FPGA_RESETn
- (FM76: NC)
- (FM76: NC)
- FM86 pin Y42: MAX10_FPGA_RESETn
- These pins not
  accessible in
  AVSTx16 Mode
- (FM76: NC)
- (FM76: NC)
- (FM76: NC)
- (FM76: NC)
- (FM76: NC)
- (FM76: NC)
- (FM76: NC)
- (FM76: NC)
- (FM76: NC)
- (FM76: NC)
- Pull-ups on PG34
- (FM76: NC)
- (FM76: NC)
- (FM76: NC)
- (FM76: NC)
- PPS loopback testing.  Route short as
  possible.  Available on FM86 for internal
  testing.
- (FM76: NC)
- (FM76: NC)
- (FM76: NC)
- (FM76: NC)
- (FM76: NC)
- Pull-ups on PG38
- (FM76: NC)
- (FM76: NC)
- (FM76: NC)
- (FM76: NC)
- (FM76: NC)
- Pull-ups on PG37
- (FM76: NC)
- (FM76: NC)
- Pull-ups on PG37
- (FM76: NC)
- (FM76: NC)
- (FM76: NC)
- Pull-ups on PG8
- (FM76: NC)
- (FM76: NC)
- (FM76: NC)
- (FM76: NC)
- (FM76: NC)
- (FM76: NC)
- (FM76: NC)
- (FM76: NC)
- AVSTx16 Data, CLK, Ready, Valid
  have internal 10K pull-up
- (FM76: NC)
- (FM76: NC)
- (FM76: NC)
- (FM76: NC)
- (FM76: NC)
- (FM76: NC)
- (FM76: NC)
- Only available on FM86 for testing
- (FM76: NC)
- (FM76: NC)
- BANK 3A
- This half of Bank3A IO's are not available
  when migrating from FM86 --> FM76 package
- External termination for tuning since OCT +/-40ohm accuracy.
  OCT should be turned off when external termination is used
- Open Drain
- Pullup on pg38
- P0-P7: Default to input after
  power-on.  User must configure
  these IOs for proper QSFP/QSFPDD
  functionality.
- I2C Addr: 4Eh
sheet 17
- Bank3B is not available in Agilex FM76.
  So no IO's will be used to support Migration from FM86 --> FM76.
  BANK3B is powered down in this devkit.
- (FM76: NC)
- (FM76: NC)
- (FM76: NC)
- (FM76: NC)
- (FM76: NC)
- (FM76: NC)
- (FM76: NC)
- (FM76: NC)
- (FM76: NC)
- (FM76: NC)
- (FM76: NC)
- (FM76: NC)
- (FM76: NC)
- (FM76: NC)
- (FM76: NC)
- (FM76: NC)
- (FM76: NC)
- (FM76: NC)
- (FM76: NC)
- (FM76: NC)
- (FM76: NC)
- (FM76: NC)
- (FM76: NC)
- (FM76: NC)
- (FM76: NC)
- (FM76: NC)
- (FM76: NC)
- (FM76: NC)
- (FM76: NC)
- (FM76: NC)
- (FM76: NC)
- (FM76: NC)
- (FM76: NC)
- (FM76: NC)
- (FM76: NC)
- (FM76: NC)
- (FM76: NC)
- (FM76: NC)
- (FM76: NC)
- (FM76: NC)
- (FM76: NC)
- (FM76: NC)
- (FM76: NC)
- (FM76: NC)
- (FM76: NC)
- (FM76: NC)
- (FM76: NC)
- (FM76: NC)
- (FM76: NC)
- (FM76: NC)
- (FM76: NC)
- (FM76: NC)
- (FM76: NC)
- (FM76: NC)
- (FM76: NC)
- (FM76: NC)
- (FM76: NC)
- (FM76: NC)
- (FM76: NC)
- (FM76: NC)
- (FM76: NC)
- (FM76: NC)
- (FM76: NC)
- (FM76: NC)
- (FM76: NC)
- (FM76: NC)
- (FM76: NC)
- (FM76: NC)
- (FM76: NC)
- (FM76: NC)
- (FM76: NC)
- (FM76: NC)
- (FM76: NC)
- (FM76: NC)
- (FM76: NC)
- (FM76: NC)
- (FM76: NC)
- (FM76: NC)
- (FM76: NC)
- (FM76: NC)
- (FM76: NC)
- (FM76: NC)
- (FM76: NC)
- (FM76: NC)
- (FM76: NC)
- (FM76: NC)
- (FM76: NC)
- (FM76: NC)
- (FM76: NC)
- (FM76: NC)
- (FM76: NC)
- (FM76: NC)
- (FM76: NC)
- (FM76: NC)
- (FM76: NC)
- (FM76: NC)
- BANK 3B available only in FM86, not FM76
sheet 18
- Bank3C is not available in Agilex FM76.
  So no IO's will be used to support Migration from FM86 --> FM76.
  Bank3C is powered down in this devkit
- Only half of Bank3C migrates from FM86 --> FM76
- (FM76: NC)
- (FM76: NC)
- (FM76: NC)
- (FM76: NC)
- (FM76: NC)
- (FM76: NC)
- (FM76: NC)
- (FM76: NC)
- (FM76: NC)
- (FM76: NC)
- (FM76: NC)
- (FM76: NC)
- (FM76: NC)
- (FM76: NC)
- (FM76: NC)
- (FM76: NC)
- (FM76: NC)
- (FM76: NC)
- (FM76: NC)
- (FM76: NC)
- (FM76: NC)
- (FM76: NC)
- (FM76: NC)
- (FM76: NC)
- (FM76: NC)
- (FM76: NC)
- (FM76: NC)
- (FM76: NC)
- (FM76: NC)
- (FM76: NC)
- (FM76: NC)
- (FM76: NC)
- (FM76: NC)
- (FM76: NC)
- (FM76: NC)
- (FM76: NC)
- (FM76: NC)
- (FM76: NC)
- (FM76: NC)
- (FM76: NC)
- (FM76: NC)
- (FM76: NC)
- (FM76: NC)
- (FM76: NC)
- (FM76: NC)
- (FM76: NC)
- (FM76: NC)
- (FM76: NC)
- Not available in FM76
- Available in FM86 and FM76
sheet 19
- BYTE4: 32-39
  (ECC)
- BYTE1: 8-15
- BYTE3: 24-31
- Place near RZQ pin
- BYTE2: 16-23
- BYTE0: 0-7
- BANK 3D available in both FM86, FM76
- External termination for tuning since OCT +/-40ohm accuracy.
  OCT should be turned off when external termination is used
sheet 20
- CXL PCIEx4
- CXL PCIEx4
- P/N swap for routing, IP must reswap
- P/N swap for routing, IP must reswap
- QSFP-56
- QSFP-56
- P/N swap for routing, IP must reswap
- P/N swap for routing, IP must reswap
- P/N swap for routing, IP must reswap
- QSFPDD-56
- QSFPDD-56
- P/N swap for routing, IP must reswap
- P/N swap for routing, IP must reswap
- P/N swap for routing, IP must reswap
- LVPECL INPUTS
- Vdiff = 0.6V to 1.7V
- LVPECL INPUTS
- Vdiff = 0.6V to 1.7V
- LVPECL INPUTS
- LVPECL INPUTS
- LVPECL INPUTS
- LVPECL INPUTS
- BANK 12C, F-TILE
- External termination for tuning since OCT +/-40ohm accuracy.
  OCT should be turned off when external termination is used
- Termination is integrated ito Si53254 clock driver
  External termination provided for tuning.
- External termination for tuning since OCT +/-40ohm accuracy.
  OCT should be turned off when external termination is used
- Termination is integrated ito Si53254 clock driver
  External termination provided for tuning.
sheet 21
- Vdiff = 0.6V to 1.7V
- LVPECL INPUTS
- LVPECL INPUTS
- Vdiff = 0.6V to 1.7V
- BANK 13A, F-TILE
- Termination is integrated ito Si53254 clock driver
  External termination provided for tuning.
- Termination is integrated ito Si53254 clock driver
  External termination provided for tuning.
- External termination for tuning since OCT +/-40ohm accuracy.
  OCT should be turned off when external termination is used
- External termination for tuning since OCT +/-40ohm accuracy.
  OCT should be turned off when external termination is used
